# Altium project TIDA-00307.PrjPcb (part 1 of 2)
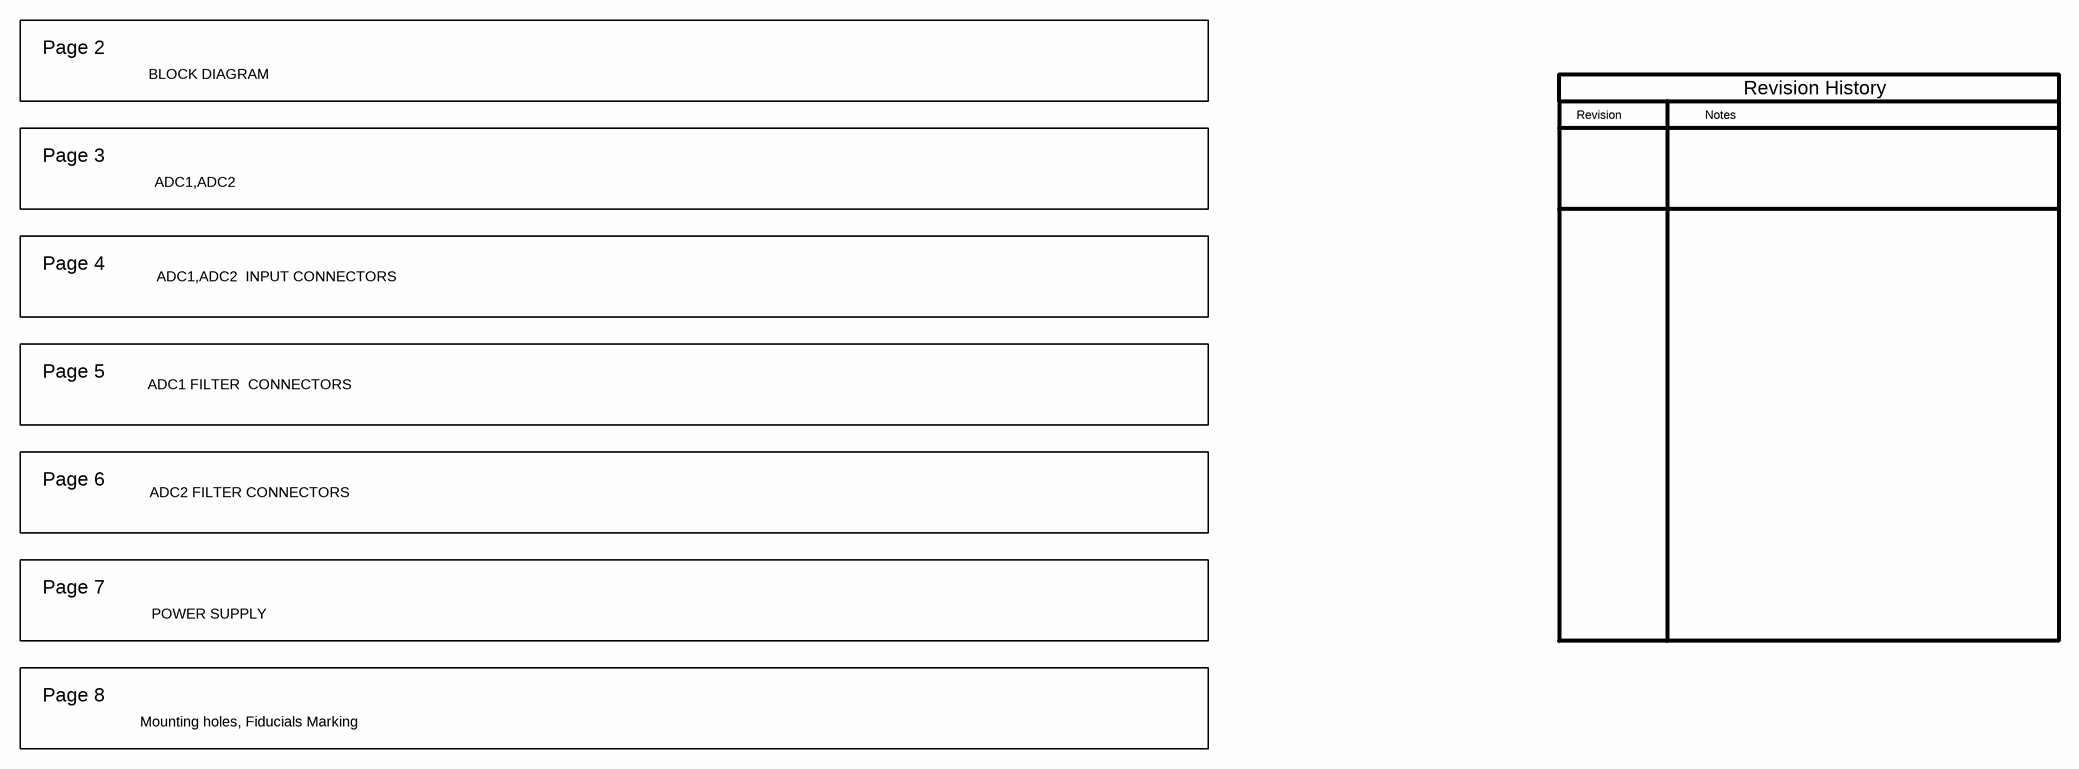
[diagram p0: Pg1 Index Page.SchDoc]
CopyrightYear: 2013; PCB_Layout: Who did the Layout?; PCB_Rev: E2; PRJ_Customer: Public Release; PRJ_Engineer: Srinivas K.; PRJ_Number: TIDA-00307; PRJ_Title: AFE-MERGING UNIT; SCH_Rev: E2; TechSupport: http://www.ti.com/support
8 sheets, 313 parts. Net scope: flat (ports and power ports of the same name join across sheets).
Board file: TIDA-00307_REV_E2.PcbDoc
Sheets:
  Pg1 Index Page.SchDoc
  Pg2 Block Diagram.SchDoc
  Pg3  ADC1,ADC2.SchDoc
  Pg4 ADC1,ADC2 INPUTS.SchDoc
  Pg5 ADC1 FILTERS.SchDoc
  Pg6 ADC2 FILTERS.SchDoc
  Pg7 Power Supply.SchDoc
  Pg8 Hardware.SchDoc

## Sheet Pg1 Index Page.SchDoc
size 431 x 279 mm; Date: Not shown in title block; ApprovedBy: Not shown in title block; CheckedBy: Not shown in title block; Author: Not shown in title block; CompanyName: Not shown in title block; Engineer: Not shown in title block; Organization: Not shown in title block; Address1: Not shown in title block; Address2: Not shown in title block; Address3: Not shown in title block; Address4: Not shown in title block; DocumentNumber: 1; Revision: E2; SheetNumber: 1; SheetTotal: 8; PageSetup: Record=PageOptions|CenterHorizontal=True|CenterVertical=True|PrintScale=1.00|XCorrection=1.00|YCorrection=1.00|PrintKind=0|BorderSize=5000000|LeftOffset=0|BottomOffset=0|Orientation=2|PaperLength=1000|PaperWidth=1000|Scale=100|PaperSource=15|PrintQuality=600|MediaType=1|DitherType=10|PaperKind=Letter|PrintScaleMode=1

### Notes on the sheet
- Page 2
- BLOCK DIAGRAM
- Revision
- Notes
- Revision History
- Page 3
- ADC1,ADC2
- Page 4
- ADC1,ADC2  INPUT CONNECTORS
- Page 5
- ADC1 FILTER  CONNECTORS
- Page 6
- ADC2 FILTER CONNECTORS
- Page 7
- POWER SUPPLY
- Page 8
- Mounting holes, Fiducials Marking

## Sheet Pg2 Block Diagram.SchDoc
size 431 x 279 mm; VersionControl_RevNumber: E2; Date: Not shown in title block; ApprovedBy: Not shown in title block; CheckedBy: Not shown in title block; Author: Not shown in title block; CompanyName: Not shown in title block; Engineer: Not shown in title block; Organization: Not shown in title block; Address1: Not shown in title block; Address2: Not shown in title block; Address3: Not shown in title block; Address4: Not shown in title block; DocumentNumber: 2; Revision: E2; SheetNumber: 2; SheetTotal: 8; PageSetup: Record=PageOptions|CenterHorizontal=True|CenterVertical=True|PrintScale=1.00|XCorrection=1.00|YCorrection=1.00|PrintKind=0|BorderSize=5000000|LeftOffset=0|BottomOffset=0|Orientation=2|PaperLength=1000|PaperWidth=1000|Scale=100|PaperSource=15|PrintQuality=600|MediaType=1|DitherType=10|PaperKind=Letter|PrintScaleMode=1
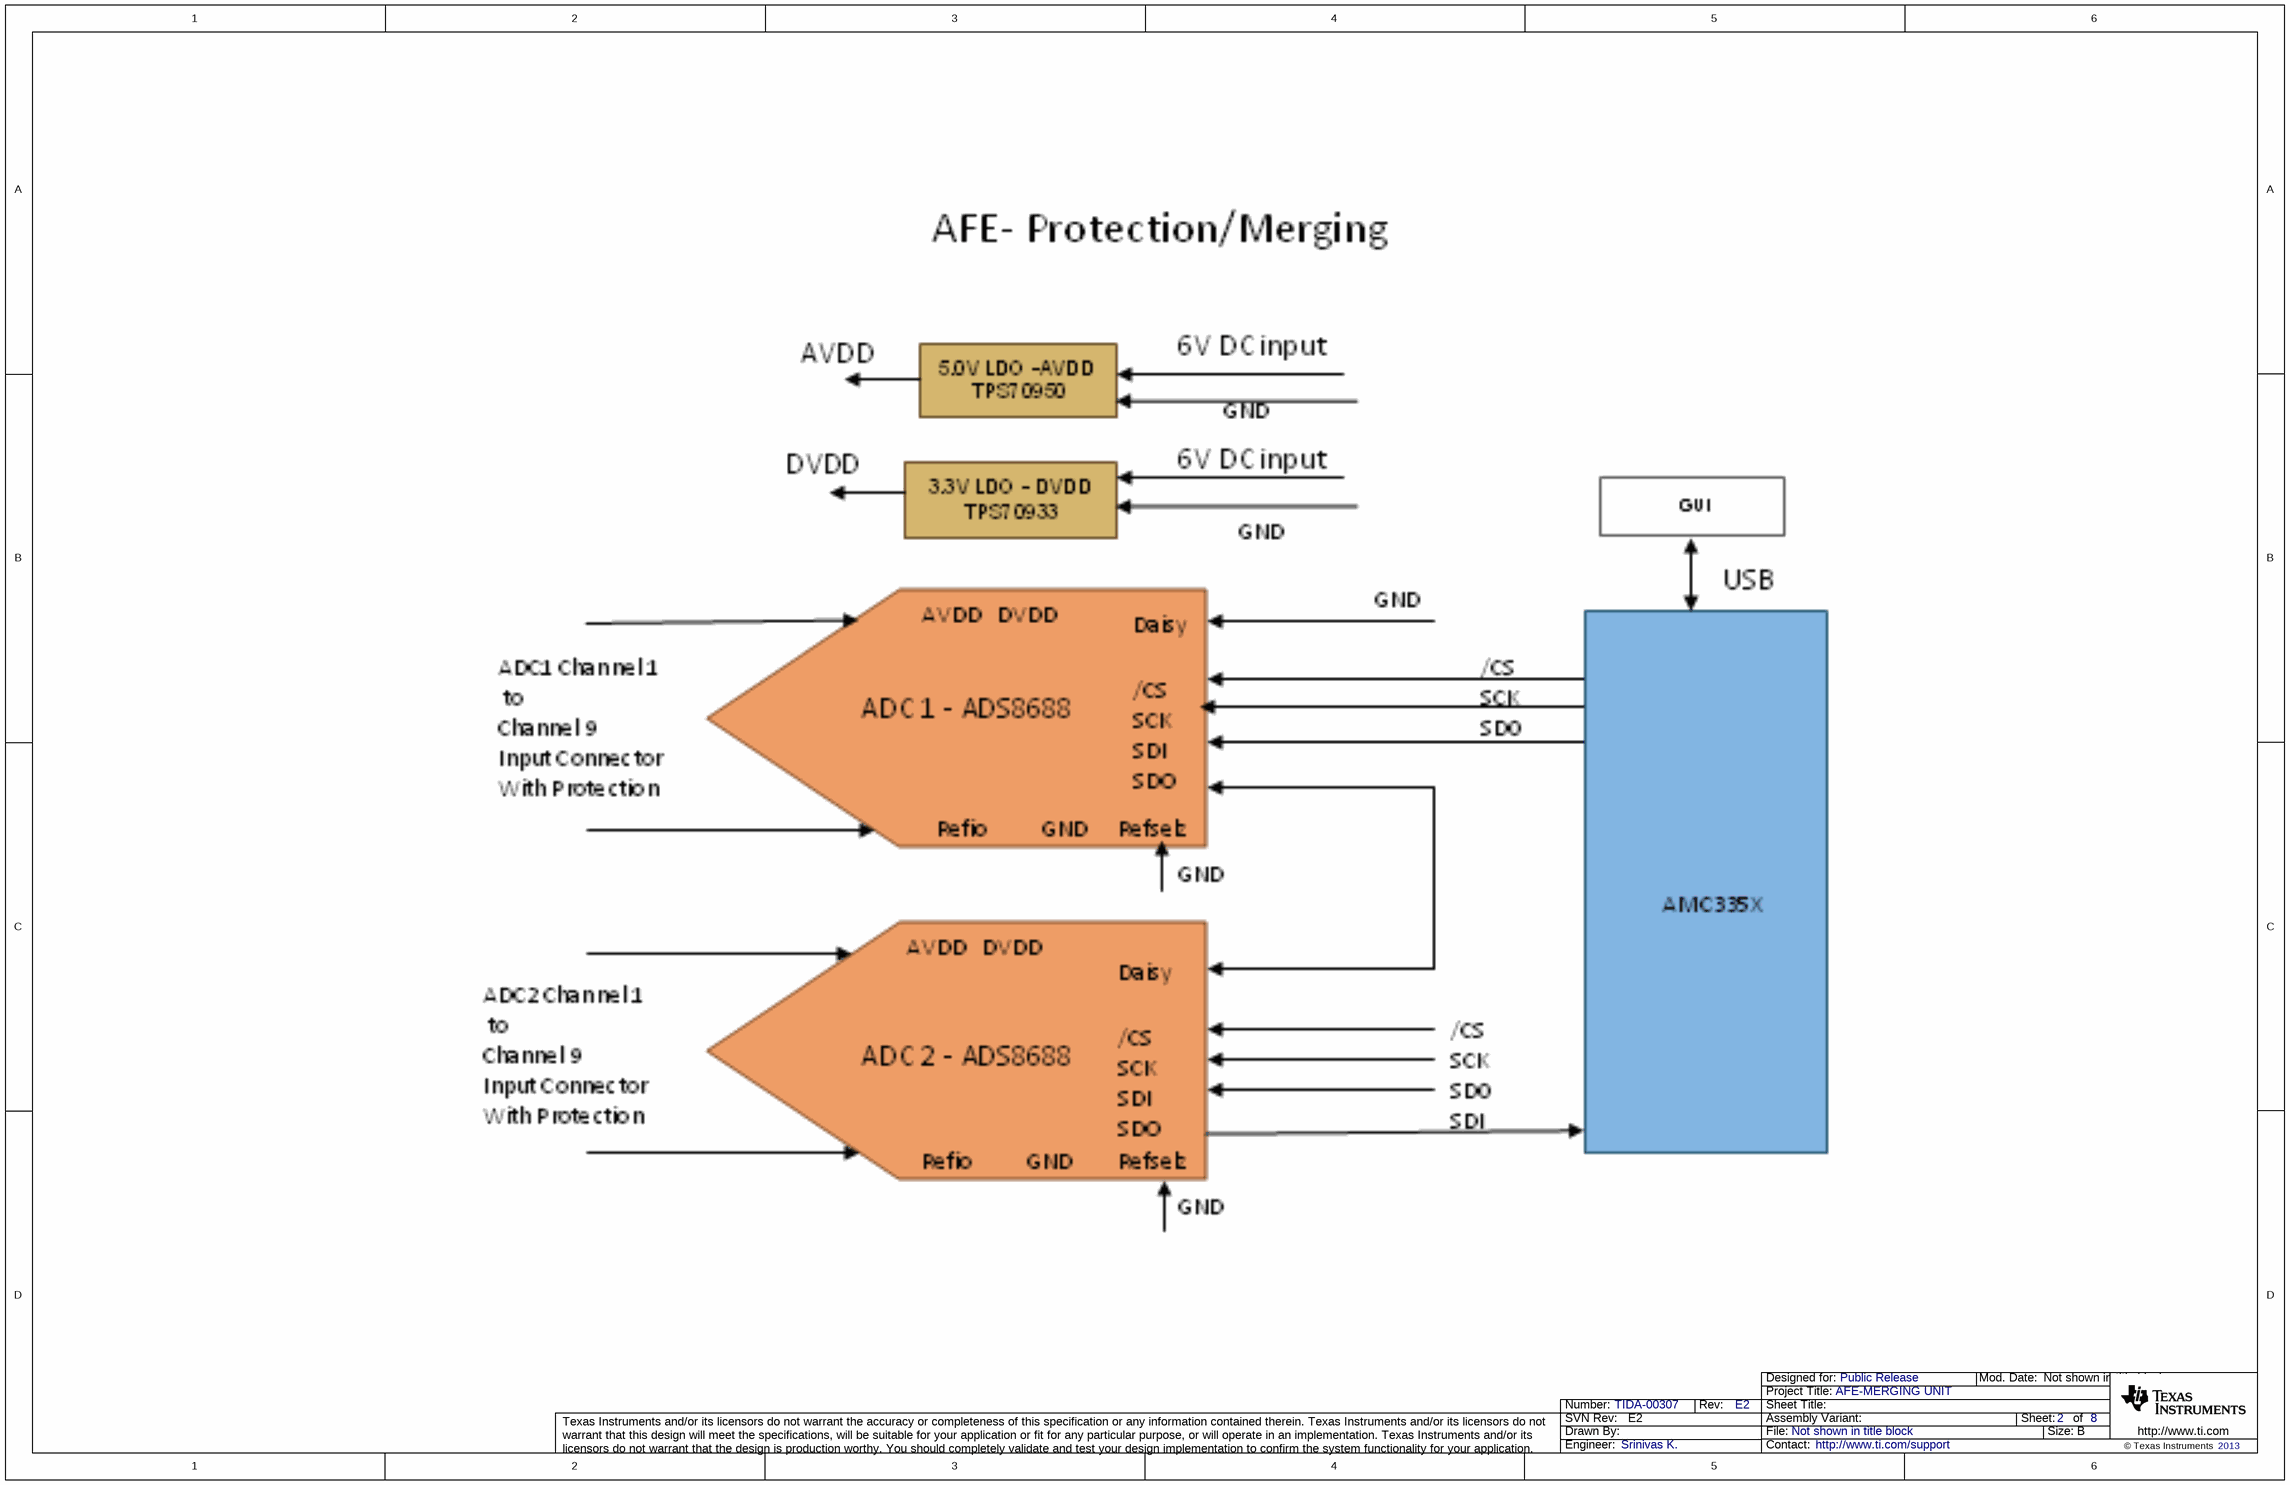
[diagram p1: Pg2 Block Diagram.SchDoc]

## Sheet Pg3  ADC1,ADC2.SchDoc
size 431 x 279 mm; Date: Not shown in title block; ApprovedBy: Not shown in title block; CheckedBy: Not shown in title block; Author: Not shown in title block; CompanyName: Not shown in title block; Engineer: Not shown in title block; Organization: Not shown in title block; Address1: Not shown in title block; Address2: Not shown in title block; Address3: Not shown in title block; Address4: Not shown in title block; DocumentNumber: 3; Revision: Use project parameter SCH_Rev; SheetNumber: 3; SheetTotal: 8; PageSetup: Record=PageOptions|CenterHorizontal=True|CenterVertical=True|PrintScale=1.00|XCorrection=1.00|YCorrection=1.00|PrintKind=0|BorderSize=5000000|LeftOffset=0|BottomOffset=0|Orientation=2|PaperLength=1000|PaperWidth=1000|Scale=100|PaperSource=15|PrintQuality=600|MediaType=1|DitherType=10|PaperKind=Letter|PrintScaleMode=1
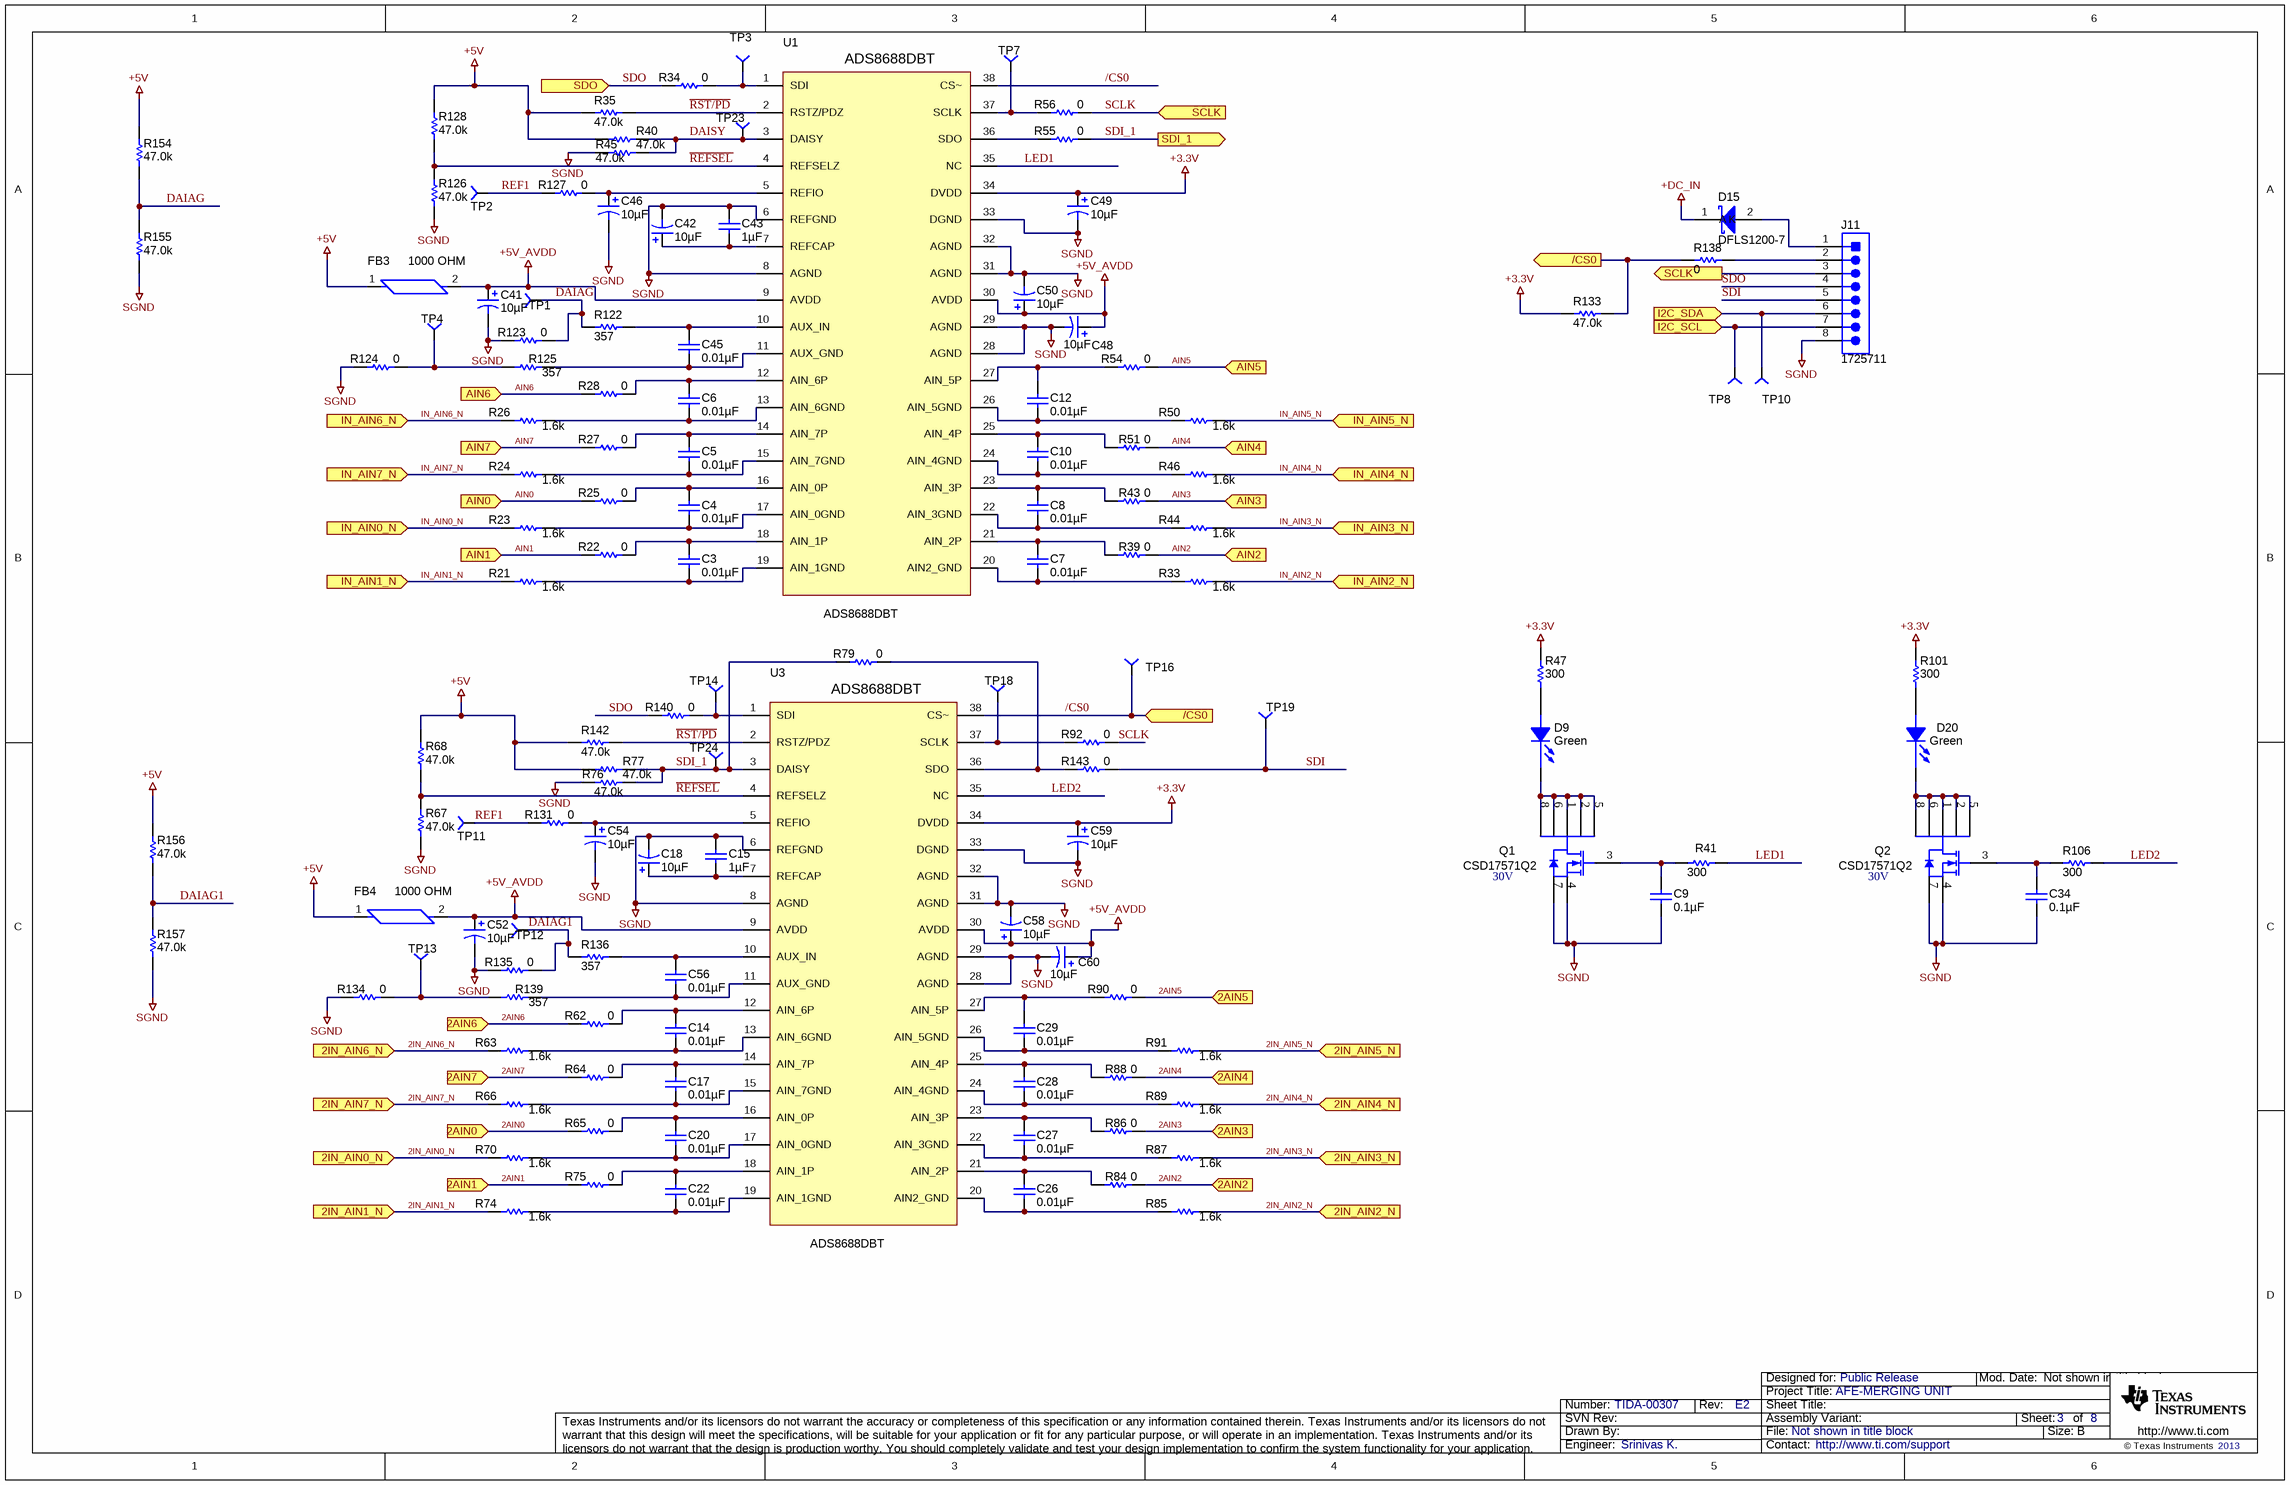
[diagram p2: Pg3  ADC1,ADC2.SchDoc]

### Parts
C3  ValueDisplayed: 0.01µF  [0603]  (hidden comment: 06031C103JAT2A)
C4  ValueDisplayed: 0.01µF  [0603]  (hidden comment: 06031C103JAT2A)
C5  ValueDisplayed: 0.01µF  [0603]  (hidden comment: 06031C103JAT2A)
C6  ValueDisplayed: 0.01µF  [0603]  (hidden comment: 06031C103JAT2A)
C7  ValueDisplayed: 0.01µF  [0603]  (hidden comment: 06031C103JAT2A)
C8  ValueDisplayed: 0.01µF  [0603]  (hidden comment: 06031C103JAT2A)
C9  ValueDisplayed: 0.1µF  [0603]  (hidden comment: 06033C104JAT2A)
C10  ValueDisplayed: 0.01µF  [0603]  (hidden comment: 06031C103JAT2A)
C12  ValueDisplayed: 0.01µF  [0603]  (hidden comment: 06031C103JAT2A)
C14  ValueDisplayed: 0.01µF  [0603]  (hidden comment: 06031C103JAT2A)
C15  ValueDisplayed: 1µF  [0603]  (hidden comment: EMK107B7105KA-T)
C17  ValueDisplayed: 0.01µF  [0603]  (hidden comment: 06031C103JAT2A)
C18  ValueDisplayed: 10µF  [3528-21]  (hidden comment: T491B106K016AT)
C20  ValueDisplayed: 0.01µF  [0603]  (hidden comment: 06031C103JAT2A)
C22  ValueDisplayed: 0.01µF  [0603]  (hidden comment: 06031C103JAT2A)
C26  ValueDisplayed: 0.01µF  [0603]  (hidden comment: 06031C103JAT2A)
C27  ValueDisplayed: 0.01µF  [0603]  (hidden comment: 06031C103JAT2A)
C28  ValueDisplayed: 0.01µF  [0603]  (hidden comment: 06031C103JAT2A)
C29  ValueDisplayed: 0.01µF  [0603]  (hidden comment: 06031C103JAT2A)
C34  ValueDisplayed: 0.1µF  [0603]  (hidden comment: 06033C104JAT2A)
C41  ValueDisplayed: 10µF  [3528-21]  (hidden comment: T491B106K016AT)
C42  ValueDisplayed: 10µF  [3528-21]  (hidden comment: T491B106K016AT)
C43  ValueDisplayed: 1µF  [0603]  (hidden comment: EMK107B7105KA-T)
C45  ValueDisplayed: 0.01µF  [0603]  (hidden comment: 06031C103JAT2A)
C46  ValueDisplayed: 10µF  [3528-21]  (hidden comment: T491B106K016AT)
C48  ValueDisplayed: 10µF  [3528-21]  (hidden comment: T491B106K016AT)
C49  ValueDisplayed: 10µF  [3528-21]  (hidden comment: T491B106K016AT)
C50  ValueDisplayed: 10µF  [3528-21]  (hidden comment: T491B106K016AT)
C52  ValueDisplayed: 10µF  [3528-21]  (hidden comment: T491B106K016AT)
C54  ValueDisplayed: 10µF  [3528-21]  (hidden comment: T491B106K016AT)
C56  ValueDisplayed: 0.01µF  [0603]  (hidden comment: 06031C103JAT2A)
C58  ValueDisplayed: 10µF  [3528-21]  (hidden comment: T491B106K016AT)
C59  ValueDisplayed: 10µF  [3528-21]  (hidden comment: T491B106K016AT)
C60  ValueDisplayed: 10µF  [3528-21]  (hidden comment: T491B106K016AT)
D9  value Green  [LED0603AA]  (hidden comment: LED_LG L29K-G2J1-24-Z)
D15  DFLS1200-7  [powerDI123]
D20  value Green  [LED0603AA]  (hidden comment: LED_LG L29K-G2J1-24-Z)
FB3  1000 OHM  [FB0603]
FB4  1000 OHM  [FB0603]
J11  1725711  [CONN_1725711]
Q1  CSD17571Q2  value 30V  [SON_CSD17571Q2]
Q2  CSD17571Q2  value 30V  [SON_CSD17571Q2]
R21  value 1.6k  [0603]  (hidden comment: CRCW06031K60JNEA)
R22  value 0  [0603]  (hidden comment: RC0603JR-070RL)
R23  value 1.6k  [0603]  (hidden comment: CRCW06031K60JNEA)
R24  value 1.6k  [0603]  (hidden comment: CRCW06031K60JNEA)
R25  value 0  [0603]  (hidden comment: RC0603JR-070RL)
R26  value 1.6k  [0603]  (hidden comment: CRCW06031K60JNEA)
R27  value 0  [0603]  (hidden comment: RC0603JR-070RL)
R28  value 0  [0603]  (hidden comment: RC0603JR-070RL)
R33  value 1.6k  [0603]  (hidden comment: CRCW06031K60JNEA)
R34  value 0  [0603]  (hidden comment: RC0603JR-070RL)
R35  value 47.0k  [0603]  (hidden comment: CRCW060347K0FKEA)
R39  value 0  [0603]  (hidden comment: RC0603JR-070RL)
R40  value 47.0k  [0603]  (hidden comment: CRCW060347K0FKEA)
R41  value 300  [0603]  (hidden comment: CRCW0603300RJNEA)
R43  value 0  [0603]  (hidden comment: RC0603JR-070RL)
R44  value 1.6k  [0603]  (hidden comment: CRCW06031K60JNEA)
R45  value 47.0k  [0603]  (hidden comment: CRCW060347K0FKEA)
R46  value 1.6k  [0603]  (hidden comment: CRCW06031K60JNEA)
R47  value 300  [0603]  (hidden comment: CRCW0603300RJNEA)
R50  value 1.6k  [0603]  (hidden comment: CRCW06031K60JNEA)
R51  value 0  [0603]  (hidden comment: RC0603JR-070RL)
R54  value 0  [0603]  (hidden comment: RC0603JR-070RL)
R55  value 0  [0603]  (hidden comment: RC0603JR-070RL)
R56  value 0  [0603]  (hidden comment: RC0603JR-070RL)
R62  value 0  [0603]  (hidden comment: RC0603JR-070RL)
R63  value 1.6k  [0603]  (hidden comment: CRCW06031K60JNEA)
R64  value 0  [0603]  (hidden comment: RC0603JR-070RL)
R65  value 0  [0603]  (hidden comment: RC0603JR-070RL)
R66  value 1.6k  [0603]  (hidden comment: CRCW06031K60JNEA)
R67  value 47.0k  [0603]  (hidden comment: CRCW060347K0FKEA)
R68  value 47.0k  [0603]  (hidden comment: CRCW060347K0FKEA)
R70  value 1.6k  [0603]  (hidden comment: CRCW06031K60JNEA)
R74  value 1.6k  [0603]  (hidden comment: CRCW06031K60JNEA)
R75  value 0  [0603]  (hidden comment: RC0603JR-070RL)
R76  value 47.0k  [0603]  (hidden comment: CRCW060347K0FKEA)
R77  value 47.0k  [0603]  (hidden comment: CRCW060347K0FKEA)
R79  value 0  [0603]  (hidden comment: RC0603JR-070RL)
R84  value 0  [0603]  (hidden comment: RC0603JR-070RL)
R85  value 1.6k  [0603]  (hidden comment: CRCW06031K60JNEA)
R86  value 0  [0603]  (hidden comment: RC0603JR-070RL)
R87  value 1.6k  [0603]  (hidden comment: CRCW06031K60JNEA)
R88  value 0  [0603]  (hidden comment: RC0603JR-070RL)
R89  value 1.6k  [0603]  (hidden comment: CRCW06031K60JNEA)
R90  value 0  [0603]  (hidden comment: RC0603JR-070RL)
R91  value 1.6k  [0603]  (hidden comment: CRCW06031K60JNEA)
R92  value 0  [0603]  (hidden comment: RC0603JR-070RL)
R101  value 300  [0603]  (hidden comment: CRCW0603300RJNEA)
R106  value 300  [0603]  (hidden comment: CRCW0603300RJNEA)
R122  value 357  [0603]  (hidden comment: CRCW0603357RFKEA)
R123  value 0  [0603]  (hidden comment: RC0603JR-070RL)
R124  value 0  [0603]  (hidden comment: RC0603JR-070RL)
R125  value 357  [0603]  (hidden comment: CRCW0603357RFKEA)
R126  value 47.0k  [0603]  (hidden comment: CRCW060347K0FKEA)
R127  value 0  [0603]  (hidden comment: RC0603JR-070RL)
R128  value 47.0k  [0603]  (hidden comment: CRCW060347K0FKEA)
R131  value 0  [0603]  (hidden comment: RC0603JR-070RL)
R133  value 47.0k  [0603]  (hidden comment: CRCW060347K0FKEA)
R134  value 0  [0603]  (hidden comment: RC0603JR-070RL)
R135  value 0  [0603]  (hidden comment: RC0603JR-070RL)
R136  value 357  [0603]  (hidden comment: CRCW0603357RFKEA)
R138  value 0  [0603]  (hidden comment: RC0603JR-070RL)
R139  value 357  [0603]  (hidden comment: CRCW0603357RFKEA)
R140  value 0  [0603]  (hidden comment: RC0603JR-070RL)
R142  value 47.0k  [0603]  (hidden comment: CRCW060347K0FKEA)
R143  value 0  [0603]  (hidden comment: RC0603JR-070RL)
R154  value 47.0k  [0603]  (hidden comment: CRCW060347K0FKEA)
R155  value 47.0k  [0603]  (hidden comment: CRCW060347K0FKEA)
R156  value 47.0k  [0603]  (hidden comment: CRCW060347K0FKEA)
R157  value 47.0k  [0603]  (hidden comment: CRCW060347K0FKEA)
TP1  TP1_PD40_D0.5_S50  [TP1_PD40_D0.5_S50]  (value not drawn)
TP2  TP1_PD40_D0.5_S50  [TP1_PD40_D0.5_S50]  (value not drawn)
TP3  TP1_PD40_D0.5_S50  [TP1_PD40_D0.5_S50]  (value not drawn)
TP4  TP1_PD40_D0.5_S50  [TP1_PD40_D0.5_S50]  (value not drawn)
TP7  TP1_PD40_D0.5_S50  [TP1_PD40_D0.5_S50]  (value not drawn)
TP8  TP1_PD40_D0.5_S50  [TP1_PD40_D0.5_S50]  (value not drawn)
TP10  TP1_PD40_D0.5_S50  [TP1_PD40_D0.5_S50]  (value not drawn)
TP11  TP1_PD40_D0.5_S50  [TP1_PD40_D0.5_S50]  (value not drawn)
TP12  TP1_PD40_D0.5_S50  [TP1_PD40_D0.5_S50]  (value not drawn)
TP13  TP1_PD40_D0.5_S50  [TP1_PD40_D0.5_S50]  (value not drawn)
TP14  TP1_PD40_D0.5_S50  [TP1_PD40_D0.5_S50]  (value not drawn)
TP16  TP1_PD40_D0.5_S50  [TP1_PD40_D0.5_S50]  (value not drawn)
TP18  TP1_PD40_D0.5_S50  [TP1_PD40_D0.5_S50]  (value not drawn)
TP19  TP1_PD40_D0.5_S50  [TP1_PD40_D0.5_S50]  (value not drawn)
TP23  TP1_PD40_D0.5_S50  [TP1_PD40_D0.5_S50]  (value not drawn)
TP24  TP1_PD40_D0.5_S50  [TP1_PD40_D0.5_S50]  (value not drawn)
U1  ADS8688DBT  [DBT0038A_M]
U3  ADS8688DBT  [DBT0038A_M]

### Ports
2AIN0 (in), 2AIN1 (in), 2AIN2 (in), 2AIN3 (in), 2AIN4 (in), 2AIN5 (in), 2AIN6 (in), 2AIN7 (in), 2IN_AIN0_N (in), 2IN_AIN1_N (in), 2IN_AIN2_N (in), 2IN_AIN3_N (in), 2IN_AIN4_N (in), 2IN_AIN5_N (in), 2IN_AIN6_N (in), 2IN_AIN7_N (in), /CS0 (in), /CS0 (out), AIN0 (in), AIN1 (in), AIN2 (in), AIN3 (in), AIN4 (in), AIN5 (in), AIN6 (in), AIN7 (in), I2C_SCL (in), I2C_SDA (in), IN_AIN0_N (in), IN_AIN1_N (in), IN_AIN2_N (in), IN_AIN3_N (in), IN_AIN4_N (in), IN_AIN5_N (in), IN_AIN6_N (in), IN_AIN7_N (in), SCLK (in), SCLK (out), SDI_1 (out), SDO (in)

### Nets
+3.3V: C49.1(+) C59.1(+) R47.2 R101.2 R133.1 U1.34(DVDD) U3.34(DVDD)
+5V: FB3.1 FB4.1 R35.1 R40.1 R68.1 R77.1 R128.1 R142.1 R154.2 R156.2
+5V_AVDD: C41.1(+) C48.1(+) C50.1(+) C52.1(+) C58.1(+) C60.1(+) FB3.2 FB4.2 U1.9(AVDD) U1.30(AVDD) U3.9(AVDD) U3.30(AVDD)
+DC_IN: D15.1(K)
SGND: C9.2 C15.1 C18.2(-) C34.2 C41.2(-) C42.2(-) C43.1 C46.2(-) C48.2(-) C49.2(-) C50.2(-) C52.2(-) C54.2(-) C58.2(-) C59.2(-) C60.2(-) J11.8 Q1.4(S) Q1.7(S) Q2.4(S) Q2.7(S) R45.1 R67.2 R76.1 R123.1 R124.1 R126.2 R134.1 R135.1 R155.1 R157.1 U1.6(REFGND) U1.8(AGND) U1.28(AGND) U1.29(AGND) U1.31(AGND) U1.32(AGND) U1.33(DGND) U3.6(REFGND) U3.8(AGND) U3.28(AGND) U3.29(AGND) U3.31(AGND) U3.32(AGND) U3.33(DGND)
2AIN0: R65.1 ; port 2AIN0
2AIN1: R75.1 ; port 2AIN1
2AIN2: R84.2 ; port 2AIN2
2AIN3: R86.2 ; port 2AIN3
2AIN4: R88.2 ; port 2AIN4
2AIN5: R90.2 ; port 2AIN5
2AIN6: R62.1 ; port 2AIN6
2AIN7: R64.1 ; port 2AIN7
2IN_AIN0_N: R70.1 ; port 2IN_AIN0_N
2IN_AIN1_N: R74.1 ; port 2IN_AIN1_N
2IN_AIN2_N: R85.2 ; port 2IN_AIN2_N
2IN_AIN3_N: R87.2 ; port 2IN_AIN3_N
2IN_AIN4_N: R89.2 ; port 2IN_AIN4_N
2IN_AIN5_N: R91.2 ; port 2IN_AIN5_N
2IN_AIN6_N: R63.1 ; port 2IN_AIN6_N
2IN_AIN7_N: R66.1 ; port 2IN_AIN7_N
/CS0: R133.2 R138.2 TP16.1 U1.38(CS~) U3.38(CS~) ; port /CS0
~{REFSEL}: R67.1 R68.2 R126.1 R128.2 U1.4(REFSELZ) U3.4(REFSELZ)
~{RST/PD}: R35.2 R142.2 U1.2(RSTZ/PDZ) U3.2(RSTZ/PDZ)
AIN0: R25.1 ; port AIN0
AIN1: R22.1 ; port AIN1
AIN2: R39.2 ; port AIN2
AIN3: R43.2 ; port AIN3
AIN4: R51.2 ; port AIN4
AIN5: R54.2 ; port AIN5
AIN6: R28.1 ; port AIN6
AIN7: R27.1 ; port AIN7
DAIAG: R122.1 R123.2 R154.1 R155.2 TP1.1
DAIAG1: R135.2 R136.1 R156.1 R157.2 TP12.1
DAISY: R40.2 R45.2 TP23.1 U1.3(DAISY)
I2C_SCL: J11.7 TP8.1 ; port I2C_SCL
I2C_SDA: J11.6 TP10.1 ; port I2C_SDA
IN_AIN0_N: R23.1 ; port IN_AIN0_N
IN_AIN1_N: R21.1 ; port IN_AIN1_N
IN_AIN2_N: R33.2 ; port IN_AIN2_N
IN_AIN3_N: R44.2 ; port IN_AIN3_N
IN_AIN4_N: R46.2 ; port IN_AIN4_N
IN_AIN5_N: R50.2 ; port IN_AIN5_N
IN_AIN6_N: R26.1 ; port IN_AIN6_N
IN_AIN7_N: R24.1 ; port IN_AIN7_N
LED1: R41.1 U1.35(NC)
LED2: R106.1 U3.35(NC)
REF1: R127.1 R131.1 TP2.1 TP11.1
SCLK: J11.3 R56.2 R92.2 ; port SCLK
SDI: J11.5 R143.2 TP19.1
SDI_1: R55.2 R76.2 R77.2 R79.1 TP24.1 U3.3(DAISY) ; port SDI_1
SDO: J11.4 R34.1 R140.1 ; port SDO
NetC3_1: C3.1 R22.2 U1.18(AIN_1P)
NetC3_2: C3.2 R21.2 U1.19(AIN_1GND)
NetC4_1: C4.1 R25.2 U1.16(AIN_0P)
NetC4_2: C4.2 R23.2 U1.17(AIN_0GND)
NetC5_1: C5.1 R27.2 U1.14(AIN_7P)
NetC5_2: C5.2 R24.2 U1.15(AIN_7GND)
NetC6_1: C6.1 R28.2 U1.12(AIN_6P)
NetC6_2: C6.2 R26.2 U1.13(AIN_6GND)
NetC7_1: C7.1 R39.1 U1.21(AIN_2P)
NetC7_2: C7.2 R33.1 U1.20(AIN2_GND)
NetC8_1: C8.1 R43.1 U1.23(AIN_3P)
NetC8_2: C8.2 R44.1 U1.22(AIN_3GND)
NetC9_1: C9.1 Q1.3(G) R41.2
NetC10_1: C10.1 R51.1 U1.25(AIN_4P)
NetC10_2: C10.2 R46.1 U1.24(AIN_4GND)
NetC12_1: C12.1 R54.1 U1.27(AIN_5P)
NetC12_2: C12.2 R50.1 U1.26(AIN_5GND)
NetC14_1: C14.1 R62.2 U3.12(AIN_6P)
NetC14_2: C14.2 R63.2 U3.13(AIN_6GND)
NetC15_2: C15.2 C18.1(+) U3.7(REFCAP)
NetC17_1: C17.1 R64.2 U3.14(AIN_7P)
NetC17_2: C17.2 R66.2 U3.15(AIN_7GND)
NetC20_1: C20.1 R65.2 U3.16(AIN_0P)
NetC20_2: C20.2 R70.2 U3.17(AIN_0GND)
NetC22_1: C22.1 R75.2 U3.18(AIN_1P)
NetC22_2: C22.2 R74.2 U3.19(AIN_1GND)
NetC26_1: C26.1 R84.1 U3.21(AIN_2P)
NetC26_2: C26.2 R85.1 U3.20(AIN2_GND)
NetC27_1: C27.1 R86.1 U3.23(AIN_3P)
NetC27_2: C27.2 R87.1 U3.22(AIN_3GND)
NetC28_1: C28.1 R88.1 U3.25(AIN_4P)
NetC28_2: C28.2 R89.1 U3.24(AIN_4GND)
NetC29_1: C29.1 R90.1 U3.27(AIN_5P)
NetC29_2: C29.2 R91.1 U3.26(AIN_5GND)
NetC34_1: C34.1 Q2.3(G) R106.2
NetC42_1: C42.1(+) C43.2 U1.7(REFCAP)
NetC45_1: C45.1 R122.2 U1.10(AUX_IN)
NetC45_2: C45.2 R125.2 U1.11(AUX_GND)
NetC46_1: C46.1(+) R127.2 U1.5(REFIO)
NetC54_1: C54.1(+) R131.2 U3.5(REFIO)
NetC56_1: C56.1 R136.2 U3.10(AUX_IN)
NetC56_2: C56.2 R139.2 U3.11(AUX_GND)
NetD9_1: D9.1(C) Q1.1(D) Q1.2(D) Q1.5(D) Q1.6(D) Q1.8(D)
NetD9_2: D9.2(A) R47.1
NetD15_2: D15.2(A) J11.1
NetD20_1: D20.1(C) Q2.1(D) Q2.2(D) Q2.5(D) Q2.6(D) Q2.8(D)
NetD20_2: D20.2(A) R101.1
NetJ11_2: J11.2 R138.1
NetR34_2: R34.2 TP3.1 U1.1(SDI)
NetR55_1: R55.1 U1.36(SDO)
NetR56_1: R56.1 TP7.1 U1.37(SCLK)
NetR79_2: R79.2 R143.1 U3.36(SDO)
NetR92_1: R92.1 TP18.1 U3.37(SCLK)
NetR124_2: R124.2 R125.1 TP4.1
NetR134_2: R134.2 R139.1 TP13.1
NetR140_2: R140.2 TP14.1 U3.1(SDI)

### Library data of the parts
C3-C8 C10 C12 C14 C17 C20 C22 C26-C29 C45 C56 = 06031C103JAT2A: CAP, CERM, 0.01uF, 100V, +/-5%, X7R, 0603; Manufacturer: AVX; Polarized: N; CompType: Capacitor; U/M: EA; Cap_F: 0.00000001; Tolerance_%: 5; ESR_Ohm: 0.098; Value1: 0.098 ohm; VDC_V: 100; TaMin_C: -55; TaMax_C: 125
C9 C34 = 06033C104JAT2A: CAP, CERM, 0.1uF, 25V, +/-5%, X7R, 0603; Manufacturer: AVX; Polarized: N; CompType: Capacitor; U/M: EA; Cap_F: 0.0000001; Tolerance_%: 5; ESR_Ohm: 0.05; Value1: 0.05 ohm; VDC_V: 25; TaMin_C: -55; TaMax_C: 125
C15 C43 = EMK107B7105KA-T: CAP, CERM, 1uF, 16V, +/-10%, X7R, 0603; Manufacturer: Taiyo Yuden; Polarized: N; CompType: Capacitor; U/M: EA; Cap_F: 0.000001; Tolerance_%: 10; Value1: Unknown; VDC_V: 16; TaMin_C: -55; TaMax_C: 85
C18 C41 C42 C46 C48-C50 C52 C54 C58-C60 = 293D106X9016B2TE3: CAP, TA, 10 µF, 16 V, +/- 10%, 2 ohm, SMD; Manufacturer: Vishay-Sprague; Polarized: Y; CompType: Capacitor; Value: 10uF; U/M: EA; Cap_F: 0.00001; Tolerance_%: 10; Value1: 2 ohm; VDC_V: 16; Value2: 16V; ESR_ohm: 2; IRMS_A: 0.21; TaMin_C: -55; TaMax_C: 125; Cap_Case: B
D9 D20 = LED_LG L29K-G2J1-24-Z: LED SmartLED Green 570NM; Manufacturer: OSRAM; SymbolCreator: x0120606
D15 = DFLS1200-7: Diode, Schottky, 200V, 1A, PowerDI123; Manufacturer: Diodes Inc.; U/M: EA; Vf_V: 0.85; Value2: 0.85V; Io_A: 1; Vr_V: 200; TJmax_C: 175; RJC_CperW: 7
FB3 FB4 = MMZ1608B102C: FERRITE CHIP 1000 OHM 300MA 0603; Manufacturer: TDK Corporation; CompType: Ferrite Bead
J11 = 1725711: Terminal Block, 8x1, 2.54 mm, TH; Manufacturer: Phoenix Contact; SymbolCreator: a0411947; U/M: EA
Q1 Q2 = CSD17571Q2: MOSFET, N-CH, 30V, 22A, SON 2X2 MM; Manufacturer: TEXAS INSTRUMENTS; CompType: POWER MOSFET
R21 R23 R24 R26 R33 R44 R46 R50 R63 R66 R70 R74 R85 R87 R89 R91 = CRCW06031K60JNEA: RES, 1.6k ohm, 5%, 0.1W, 0603; Manufacturer: Vishay-Dale; CompType: Resistor; Res_ohm: 1600; Value_Code: 1k60; Tolerance_%: 5; Power_W: 0.1; VDC_V: 75; TempCo: 200 ppm/C; EIA_Code: E24; U/M: EA
R22 R25 R27 R28 R34 R39 R43 R51 R54-R56 R62 R64 R65 R75 R79 R84 R86 R88 R90 R92 R123 R124 R127 R131 R134 R135 R138 R140 R143 = RC0402JR-070RL: RES, 0 ohm,5%, 0.1W, 0603; Manufacturer: Yageo America; CompType: Resistor; Value_Code: 0000; Tolerance_%: 5; Power_W: 0.1; VDC_V: 50; TempCo: 200 ppm/C; EIA_Code: E24; U/M: EA
R35 R40 R45 R67 R68 R76 R77 R126 R128 R133 R142 R154-R157 = RT0603BRD0747KL: RES, 47.0k ohm, 1%, 0.1W, 0603; Manufacturer: Vishay Dale; CompType: Resistor; Res_ohm: 47000; Value_Code: 47k0; Tolerance_%: 1; Power_W: 0.1; VDC_V: 75; TempCo: 25 ppm/C; EIA_Code: E192; U/M: EA
R41 R47 R101 R106 = CRCW0603300RJNEA: RES, 300 ohm, 5%, 0.1W, 0603; Manufacturer: Vishay-Dale; CompType: Resistor; Value_Code: 300R; Tolerance_%: 5; Power_W: 0.1; VDC_V: 75; TempCo: 200 ppm/C; EIA_Code: E24; U/M: EA
R122 R125 R136 R139 = CRCW0603357RFKEA: RES, 357 ohm, 1%, 0.1W, 0603; Manufacturer: Vishay-Dale; CompType: Resistor; Value_Code: 357R; Tolerance_%: 1; Power_W: 0.1; VDC_V: 75; TempCo: 100 ppm/C; EIA_Code: E96; U/M: EA
TP1-TP4 TP7 TP8 TP10-TP14 TP16 TP18 TP19 TP23 TP24 = TP-040_RND: Test Point 40mil pad 20mil drill; Manufacturer: STD; Description: Test Point, O.040 Hole; Value: STD
U1 U3 = ADS8688DBT: 16 bit 400KSPS 8 Channel SAR ADC; Manufacturer: TI; Alternate Manufacturer: None; SymbolCreator: a0393903; CompType: ADC IC; U/M: EA, IN, or GM

## Sheet Pg4 ADC1,ADC2 INPUTS.SchDoc
size 431 x 279 mm; Date: Not shown in title block; ApprovedBy: Not shown in title block; CheckedBy: Not shown in title block; Author: Not shown in title block; CompanyName: Not shown in title block; Engineer: Not shown in title block; Organization: Not shown in title block; Address1: Not shown in title block; Address2: Not shown in title block; Address3: Not shown in title block; Address4: Not shown in title block; DocumentNumber: 8; Revision: Use project parameter SCH_Rev; SheetNumber: 4; SheetTotal: 8; PageSetup: Record=PageOptions|CenterHorizontal=True|CenterVertical=True|PrintScale=1.00|XCorrection=1.00|YCorrection=1.00|PrintKind=0|BorderSize=5000000|LeftOffset=0|BottomOffset=0|Orientation=2|PaperLength=1000|PaperWidth=1000|Scale=100|PaperSource=15|PrintQuality=600|MediaType=1|DitherType=10|PaperKind=Letter|PrintScaleMode=1
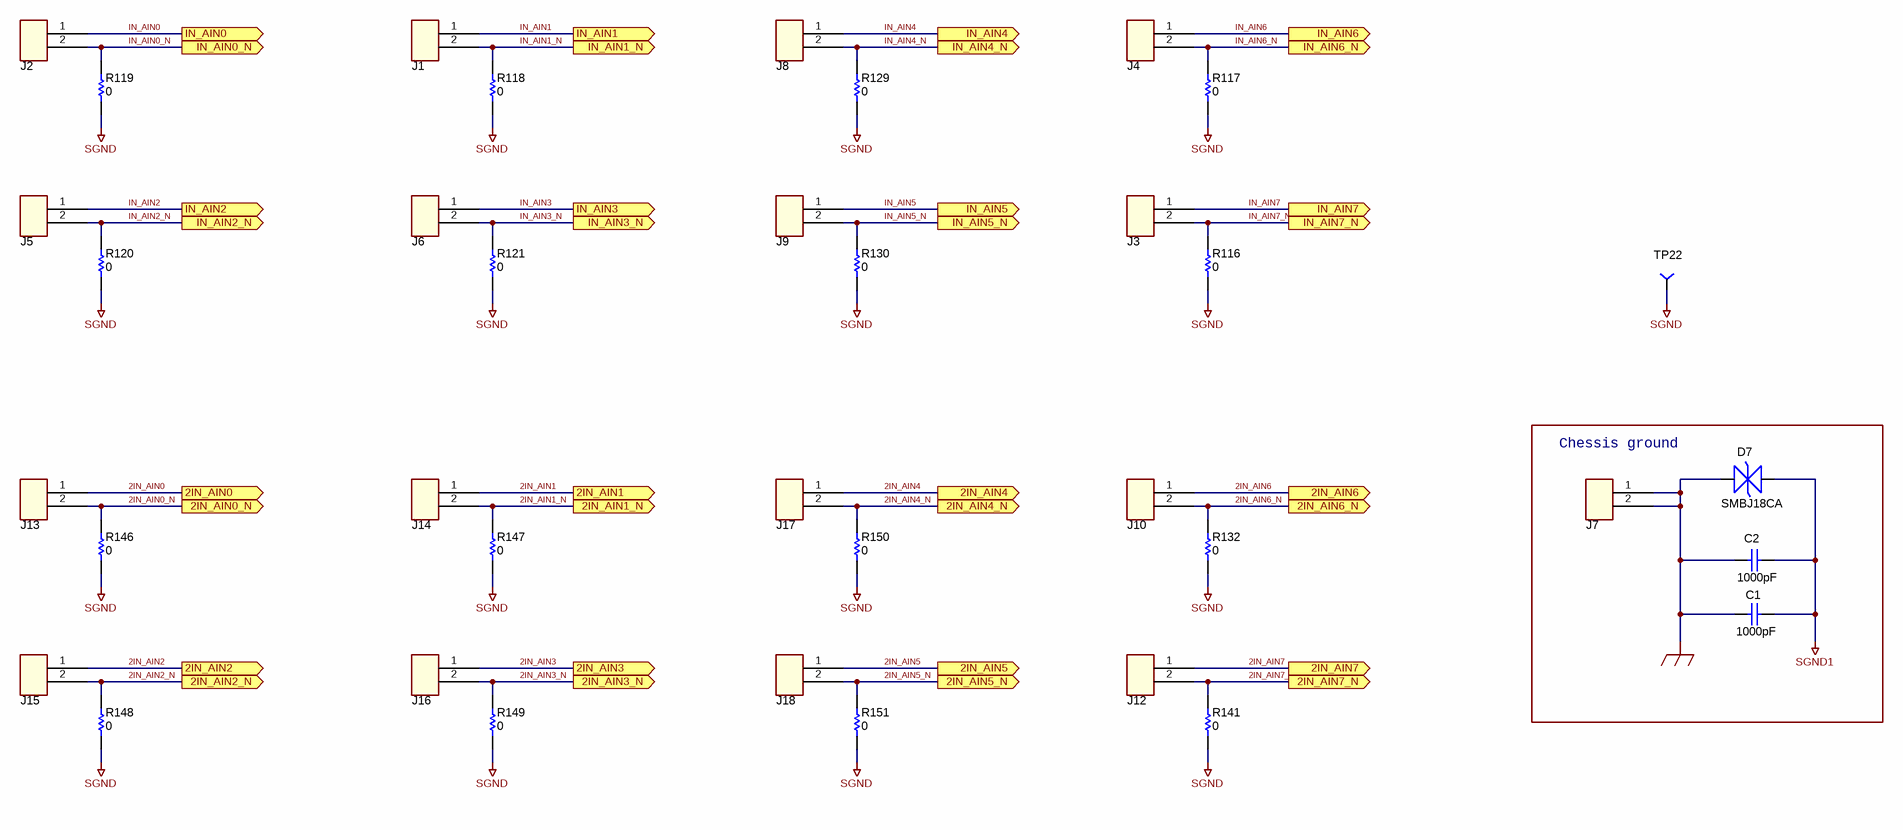
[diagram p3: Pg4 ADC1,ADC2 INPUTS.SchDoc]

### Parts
C1  value 1000pF  [1206]  (hidden comment: 202R18W102KV4E)
C2  value 1000pF  [1206]  (hidden comment: 202R18W102KV4E)
D7  SMBJ18CA  [DIO_SMB_BIAAAA]
J1  CON-OSTVN02A150  [CN2_MTB_P100_PD80_D1.1_S5.54X6.5_STACK]  (value not drawn)
J2  CON-OSTVN02A150  [CN2_MTB_P100_PD80_D1.1_S5.54X6.5_STACK]  (value not drawn)
J3  CON-OSTVN02A150  [CN2_MTB_P100_PD80_D1.1_S5.54X6.5_STACK]  (value not drawn)
J4  CON-OSTVN02A150  [CN2_MTB_P100_PD80_D1.1_S5.54X6.5_STACK]  (value not drawn)
J5  CON-OSTVN02A150  [CN2_MTB_P100_PD80_D1.1_S5.54X6.5_STACK]  (value not drawn)
J6  CON-OSTVN02A150  [CN2_MTB_P100_PD80_D1.1_S5.54X6.5_STACK]  (value not drawn)
J7  CON-OSTVN02A150  [CN2_MTB_P100_PD80_D1.1_S5.54X6.5_STACK]  (value not drawn)
J8  CON-OSTVN02A150  [CN2_MTB_P100_PD80_D1.1_S5.54X6.5_STACK]  (value not drawn)
J9  CON-OSTVN02A150  [CN2_MTB_P100_PD80_D1.1_S5.54X6.5_STACK]  (value not drawn)
J10  CON-OSTVN02A150  [CN2_MTB_P100_PD80_D1.1_S5.54X6.5_STACK]  (value not drawn)
J12  CON-OSTVN02A150  [CN2_MTB_P100_PD80_D1.1_S5.54X6.5_STACK]  (value not drawn)
J13  CON-OSTVN02A150  [CN2_MTB_P100_PD80_D1.1_S5.54X6.5_STACK]  (value not drawn)
J14  CON-OSTVN02A150  [CN2_MTB_P100_PD80_D1.1_S5.54X6.5_STACK]  (value not drawn)
J15  CON-OSTVN02A150  [CN2_MTB_P100_PD80_D1.1_S5.54X6.5_STACK]  (value not drawn)
J16  CON-OSTVN02A150  [CN2_MTB_P100_PD80_D1.1_S5.54X6.5_STACK]  (value not drawn)
J17  CON-OSTVN02A150  [CN2_MTB_P100_PD80_D1.1_S5.54X6.5_STACK]  (value not drawn)
J18  CON-OSTVN02A150  [CN2_MTB_P100_PD80_D1.1_S5.54X6.5_STACK]  (value not drawn)
R116  value 0  [1206]  (hidden comment: RC1206JR-070RL)
R117  value 0  [1206]  (hidden comment: RC1206JR-070RL)
R118  value 0  [1206]  (hidden comment: RC1206JR-070RL)
R119  value 0  [1206]  (hidden comment: RC1206JR-070RL)
R120  value 0  [1206]  (hidden comment: RC1206JR-070RL)
R121  value 0  [1206]  (hidden comment: RC1206JR-070RL)
R129  value 0  [1206]  (hidden comment: RC1206JR-070RL)
R130  value 0  [1206]  (hidden comment: RC1206JR-070RL)
R132  value 0  [1206]  (hidden comment: RC1206JR-070RL)
R141  value 0  [1206]  (hidden comment: RC1206JR-070RL)
R146  value 0  [1206]  (hidden comment: RC1206JR-070RL)
R147  value 0  [1206]  (hidden comment: RC1206JR-070RL)
R148  value 0  [1206]  (hidden comment: RC1206JR-070RL)
R149  value 0  [1206]  (hidden comment: RC1206JR-070RL)
R150  value 0  [1206]  (hidden comment: RC1206JR-070RL)
R151  value 0  [1206]  (hidden comment: RC1206JR-070RL)
TP22  TP1_PD40_D0.5_S50  [TP1_PD40_D0.5_S50]  (value not drawn)

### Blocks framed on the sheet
Chessis ground: C1 C2 D7 J7

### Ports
2IN_AIN0 (out), 2IN_AIN0_N (out), 2IN_AIN1 (out), 2IN_AIN1_N (out), 2IN_AIN2 (out), 2IN_AIN2_N (out), 2IN_AIN3 (out), 2IN_AIN3_N (out), 2IN_AIN4 (out), 2IN_AIN4_N (out), 2IN_AIN5 (out), 2IN_AIN5_N (out), 2IN_AIN6 (out), 2IN_AIN6_N (out), 2IN_AIN7 (out), 2IN_AIN7_N (out), IN_AIN0 (out), IN_AIN0_N (out), IN_AIN1 (out), IN_AIN1_N (out), IN_AIN2 (out), IN_AIN2_N (out), IN_AIN3 (out), IN_AIN3_N (out), IN_AIN4 (out), IN_AIN4_N (out), IN_AIN5 (out), IN_AIN5_N (out), IN_AIN6 (out), IN_AIN6_N (out), IN_AIN7 (out), IN_AIN7_N (out)

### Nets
GND_EARTH: C1.2 C2.2 D7.2 J7.1 J7.2
SGND: R116.1 R117.1 R118.1 R119.1 R120.1 R121.1 R129.1 R130.1 R132.1 R141.1 R146.1 R147.1 R148.1 R149.1 R150.1 R151.1 TP22.1
SGND1: C1.1 C2.1 D7.1
2IN_AIN0: J13.1 ; port 2IN_AIN0
2IN_AIN0_N: J13.2 R146.2 ; port 2IN_AIN0_N
2IN_AIN1: J14.1 ; port 2IN_AIN1
2IN_AIN1_N: J14.2 R147.2 ; port 2IN_AIN1_N
2IN_AIN2: J15.1 ; port 2IN_AIN2
2IN_AIN2_N: J15.2 R148.2 ; port 2IN_AIN2_N
2IN_AIN3: J16.1 ; port 2IN_AIN3
2IN_AIN3_N: J16.2 R149.2 ; port 2IN_AIN3_N
2IN_AIN4: J17.1 ; port 2IN_AIN4
2IN_AIN4_N: J17.2 R150.2 ; port 2IN_AIN4_N
2IN_AIN5: J18.1 ; port 2IN_AIN5
2IN_AIN5_N: J18.2 R151.2 ; port 2IN_AIN5_N
2IN_AIN6: J10.1 ; port 2IN_AIN6
2IN_AIN6_N: J10.2 R132.2 ; port 2IN_AIN6_N
2IN_AIN7: J12.1 ; port 2IN_AIN7
2IN_AIN7_N: J12.2 R141.2 ; port 2IN_AIN7_N
IN_AIN0: J2.1 ; port IN_AIN0
IN_AIN0_N: J2.2 R119.2 ; port IN_AIN0_N
IN_AIN1: J1.1 ; port IN_AIN1
IN_AIN1_N: J1.2 R118.2 ; port IN_AIN1_N
IN_AIN2: J5.1 ; port IN_AIN2
IN_AIN2_N: J5.2 R120.2 ; port IN_AIN2_N
IN_AIN3: J6.1 ; port IN_AIN3
IN_AIN3_N: J6.2 R121.2 ; port IN_AIN3_N
IN_AIN4: J8.1 ; port IN_AIN4
IN_AIN4_N: J8.2 R129.2 ; port IN_AIN4_N
IN_AIN5: J9.1 ; port IN_AIN5
IN_AIN5_N: J9.2 R130.2 ; port IN_AIN5_N
IN_AIN6: J4.1 ; port IN_AIN6
IN_AIN6_N: J4.2 R117.2 ; port IN_AIN6_N
IN_AIN7: J3.1 ; port IN_AIN7
IN_AIN7_N: J3.2 R116.2 ; port IN_AIN7_N

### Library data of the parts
C1 C2 = 202R18W102KV4E: CAP, CERM, 1000pF, 2KV 10% X7R 1206; Manufacturer: Johanson Dielectrics Inc; Polarized: N; CompType: Capacitor; Cap_F: 0.000000001; Tolerance_%: 0
D7 = SMBJ18CA: TVS 18 VOLT 600 WATT BI-DIR SMB; Manufacturer: Littelfuse Inc
J1-J10 J12-J18 = CON-OSTVN02A150: Terminal Block, 4x1, 2.54mm, TH; Manufacturer: On Shore Technology Inc; SymbolCreator: x0120606
R116-R121 R129 R130 R132 R141 R146-R151 = RC0402JR-070RL: RES, 0 ohm,5%, 0.25W, 1206; Manufacturer: Yageo America; CompType: Resistor; Value_Code: 0000; Tolerance_%: 5; Power_W: 0.1; Value2: 0.125W; VDC_V: 50; TempCo: 200 ppm/C; EIA_Code: E24; U/M: EA
TP22 = TP-040_RND: as TP1 on sheet Pg3  ADC1,ADC2

## Sheet Pg5 ADC1 FILTERS.SchDoc
size 431 x 279 mm; Date: Not shown in title block; ApprovedBy: Not shown in title block; CheckedBy: Not shown in title block; Author: Not shown in title block; CompanyName: Not shown in title block; Engineer: Not shown in title block; Organization: Not shown in title block; Address1: Not shown in title block; Address2: Not shown in title block; Address3: Not shown in title block; Address4: Not shown in title block; DocumentNumber: 4; Revision: Use project parameter SCH_Rev; SheetNumber: 5; SheetTotal: 8; PageSetup: Record=PageOptions|CenterHorizontal=True|CenterVertical=True|PrintScale=0.64|XCorrection=1.00|YCorrection=1.00|PrintKind=0|BorderSize=5000000|LeftOffset=0|BottomOffset=0|Orientation=2|PaperLength=1000|PaperWidth=1000|Scale=100|PaperSource=15|PrintQuality=600|MediaType=1|DitherType=10|PaperKind=Letter|PrintScaleMode=1
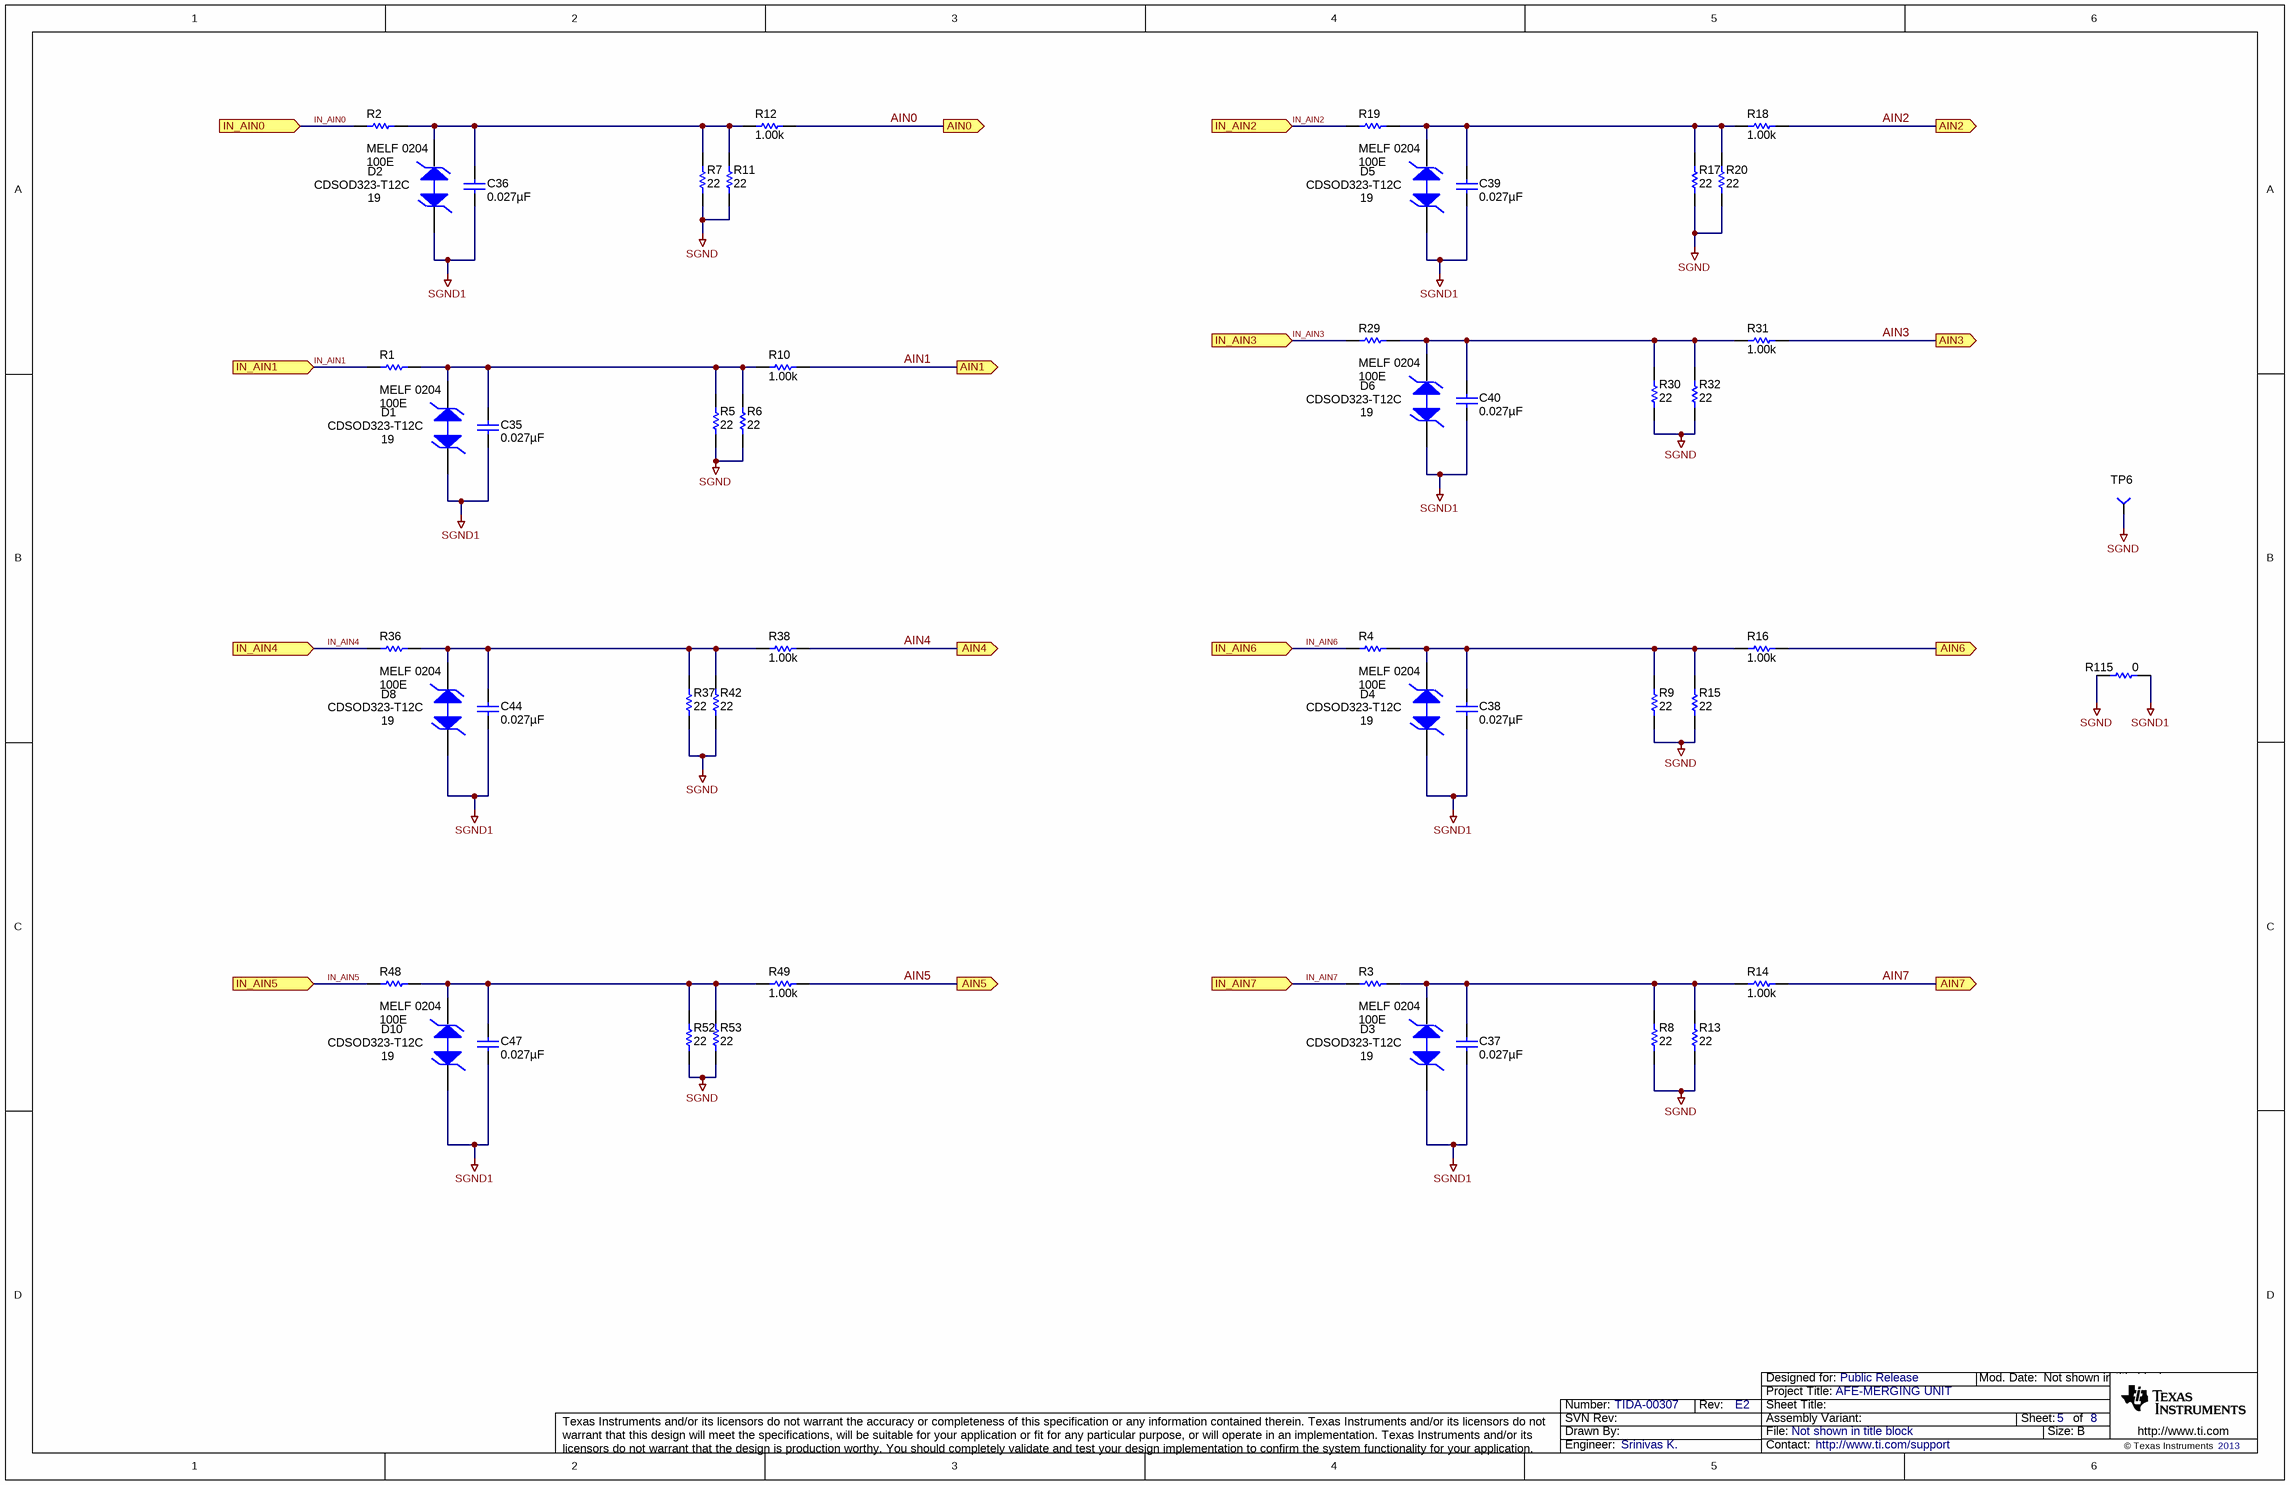
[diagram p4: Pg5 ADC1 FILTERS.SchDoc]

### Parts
C35  ValueDisplayed: 0.027µF  [1206]  (hidden comment: GRM3195C1H273JA01D)
C36  ValueDisplayed: 0.027µF  [1206]  (hidden comment: GRM3195C1H273JA01D)
C37  ValueDisplayed: 0.027µF  [1206]  (hidden comment: GRM3195C1H273JA01D)
C38  ValueDisplayed: 0.027µF  [1206]  (hidden comment: GRM3195C1H273JA01D)
C39  ValueDisplayed: 0.027µF  [1206]  (hidden comment: GRM3195C1H273JA01D)
C40  ValueDisplayed: 0.027µF  [1206]  (hidden comment: GRM3195C1H273JA01D)
C44  ValueDisplayed: 0.027µF  [1206]  (hidden comment: GRM3195C1H273JA01D)
C47  ValueDisplayed: 0.027µF  [1206]  (hidden comment: GRM3195C1H273JA01D)
D1  CDSOD323-T12C  value 19  [sod-323]
D2  CDSOD323-T12C  value 19  [sod-323]
D3  CDSOD323-T12C  value 19  [sod-323]
D4  CDSOD323-T12C  value 19  [sod-323]
D5  CDSOD323-T12C  value 19  [sod-323]
D6  CDSOD323-T12C  value 19  [sod-323]
D8  CDSOD323-T12C  value 19  [sod-323]
D10  CDSOD323-T12C  value 19  [sod-323]
R1  value 100E  PackageReference: MELF 0204  [1206]  (hidden comment: MMA02040C1000FB300)
R2  value 100E  PackageReference: MELF 0204  [1206]  (hidden comment: MMA02040C1000FB300)
R3  value 100E  PackageReference: MELF 0204  [1206]  (hidden comment: MMA02040C1000FB300)
R4  value 100E  PackageReference: MELF 0204  [1206]  (hidden comment: MMA02040C1000FB300)
R5  value 22  [0603]  (hidden comment: CRCW060322R0FKEA)
R6  value 22  [0603]  (hidden comment: CRCW060322R0FKEA)
R7  value 22  [0603]  (hidden comment: CRCW060322R0FKEA)
R8  value 22  [0603]  (hidden comment: CRCW060322R0FKEA)
R9  value 22  [0603]  (hidden comment: CRCW060322R0FKEA)
R10  value 1.00k  [0603]  (hidden comment: CRCW06031K00FKEA)
R11  value 22  [0603]  (hidden comment: CRCW060322R0FKEA)
R12  value 1.00k  [0603]  (hidden comment: CRCW06031K00FKEA)
R13  value 22  [0603]  (hidden comment: CRCW060322R0FKEA)
R14  value 1.00k  [0603]  (hidden comment: CRCW06031K00FKEA)
R15  value 22  [0603]  (hidden comment: CRCW060322R0FKEA)
R16  value 1.00k  [0603]  (hidden comment: CRCW06031K00FKEA)
R17  value 22  [0603]  (hidden comment: CRCW060322R0FKEA)
R18  value 1.00k  [0603]  (hidden comment: CRCW06031K00FKEA)
R19  value 100E  PackageReference: MELF 0204  [1206]  (hidden comment: MMA02040C1000FB300)
R20  value 22  [0603]  (hidden comment: CRCW060322R0FKEA)
R29  value 100E  PackageReference: MELF 0204  [1206]  (hidden comment: MMA02040C1000FB300)
R30  value 22  [0603]  (hidden comment: CRCW060322R0FKEA)
R31  value 1.00k  [0603]  (hidden comment: CRCW06031K00FKEA)
R32  value 22  [0603]  (hidden comment: CRCW060322R0FKEA)
R36  value 100E  PackageReference: MELF 0204  [1206]  (hidden comment: MMA02040C1000FB300)
R37  value 22  [0603]  (hidden comment: CRCW060322R0FKEA)
R38  value 1.00k  [0603]  (hidden comment: CRCW06031K00FKEA)
R42  value 22  [0603]  (hidden comment: CRCW060322R0FKEA)
R48  value 100E  PackageReference: MELF 0204  [1206]  (hidden comment: MMA02040C1000FB300)
R49  value 1.00k  [0603]  (hidden comment: CRCW06031K00FKEA)
R52  value 22  [0603]  (hidden comment: CRCW060322R0FKEA)
R53  value 22  [0603]  (hidden comment: CRCW060322R0FKEA)
R115  value 0  [1206]  (hidden comment: RC1206JR-070RL)
TP6  TP1_PD40_D0.5_S50  [TP1_PD40_D0.5_S50]  (value not drawn)

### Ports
AIN0 (out), AIN1 (out), AIN2 (out), AIN3 (out), AIN4 (out), AIN5 (out), AIN6 (out), AIN7 (out), IN_AIN0 (in), IN_AIN1 (in), IN_AIN2 (in), IN_AIN3 (in), IN_AIN4 (in), IN_AIN5 (in), IN_AIN6 (in), IN_AIN7 (in)

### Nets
SGND: R5.1 R6.1 R7.1 R8.1 R9.1 R11.1 R13.1 R15.1 R17.1 R20.1 R30.1 R32.1 R37.1 R42.1 R52.1 R53.1 R115.1 TP6.1
SGND1: C35.2 C36.2 C37.2 C38.2 C39.2 C40.2 C44.2 C47.2 D1.2 D2.2 D3.2 D4.2 D5.2 D6.2 D8.2 D10.2 R115.2
AIN0: R12.2 ; port AIN0
AIN1: R10.2 ; port AIN1
AIN2: R18.2 ; port AIN2
AIN3: R31.2 ; port AIN3
AIN4: R38.2 ; port AIN4
AIN5: R49.2 ; port AIN5
AIN6: R16.2 ; port AIN6
AIN7: R14.2 ; port AIN7
IN_AIN0: R2.1 ; port IN_AIN0
IN_AIN1: R1.1 ; port IN_AIN1
IN_AIN2: R19.1 ; port IN_AIN2
IN_AIN3: R29.1 ; port IN_AIN3
IN_AIN4: R36.1 ; port IN_AIN4
IN_AIN5: R48.1 ; port IN_AIN5
IN_AIN6: R4.1 ; port IN_AIN6
IN_AIN7: R3.1 ; port IN_AIN7
NetC35_1: C35.1 D1.1 R1.2 R5.2 R6.2 R10.1
NetC36_1: C36.1 D2.1 R2.2 R7.2 R11.2 R12.1
NetC37_1: C37.1 D3.1 R3.2 R8.2 R13.2 R14.1
NetC38_1: C38.1 D4.1 R4.2 R9.2 R15.2 R16.1
NetC39_1: C39.1 D5.1 R17.2 R18.1 R19.2 R20.2
NetC40_1: C40.1 D6.1 R29.2 R30.2 R31.1 R32.2
NetC44_1: C44.1 D8.1 R36.2 R37.2 R38.1 R42.2
NetC47_1: C47.1 D10.1 R48.2 R49.1 R52.2 R53.2

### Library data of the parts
C35-C40 C44 C47 = GRM3195C1H273JA01D: CAP, CERM, 0.027uF, 50V, +/-5%, C0G/NP0, 1206; Manufacturer: MuRata; Polarized: N; CompType: Capacitor; U/M: EA; Cap_F: 0.000000027; Tolerance_%: 5; Value1: Unknown; VDC_V: 50; TaMin_C: -55; TaMax_C: 125
D1-D6 D8 D10 = CDSOD323-T15SC: Diode, TVS, ARRAY, 19V, SOD323; Manufacturer: Bourns Inc.
R1-R4 R19 R29 R36 R48 = MMA02040C1000FB300: RES 100 OHM .4W 1% 0204 MELF; Manufacturer: Vishay Beyschlag; CompType: Resistor; Power_W: 0.5
R5-R9 R11 R13 R15 R17 R20 R30 R32 R37 R42 R52 R53 = CRCW060322R0JNEA: RES, 22 ohm, 1%, 0.1W, 0603; Manufacturer: Vishay-Dale; CompType: Resistor; Value_Code: 22R0; Tolerance_%: 1; Power_W: 0.1; VDC_V: 75; TempCo: 200 ppm/C; EIA_Code: E24; U/M: EA
R10 R12 R14 R16 R18 R31 R38 R49 = CRCW06031K00FKEA: RES, 1.00k ohm, 1%, 0.1W, 0603; Manufacturer: Vishay-Dale; CompType: Resistor; Res_ohm: 1000; Value_Code: 1k00; Tolerance_%: 1; Power_W: 0.1; VDC_V: 75; TempCo: 100 ppm/C; EIA_Code: E96; U/M: EA
R115 = RC0402JR-070RL: as R116 on sheet Pg4 ADC1,ADC2 INPUTS
TP6 = TP-040_RND: as TP1 on sheet Pg3  ADC1,ADC2

## Sheet Pg6 ADC2 FILTERS.SchDoc
size 431 x 279 mm; Date: Not shown in title block; ApprovedBy: Not shown in title block; CheckedBy: Not shown in title block; Author: Not shown in title block; CompanyName: Not shown in title block; Engineer: Not shown in title block; Organization: Not shown in title block; Address1: Not shown in title block; Address2: Not shown in title block; Address3: Not shown in title block; Address4: Not shown in title block; DocumentNumber: 7; Revision: Use project parameter SCH_Rev; SheetNumber: 6; SheetTotal: 8; PageSetup: Record=PageOptions|CenterHorizontal=True|CenterVertical=True|PrintScale=0.64|XCorrection=1.00|YCorrection=1.00|PrintKind=0|BorderSize=5000000|LeftOffset=0|BottomOffset=0|Orientation=2|PaperLength=1000|PaperWidth=1000|Scale=100|PaperSource=15|PrintQuality=600|MediaType=1|DitherType=10|PaperKind=Letter|PrintScaleMode=1
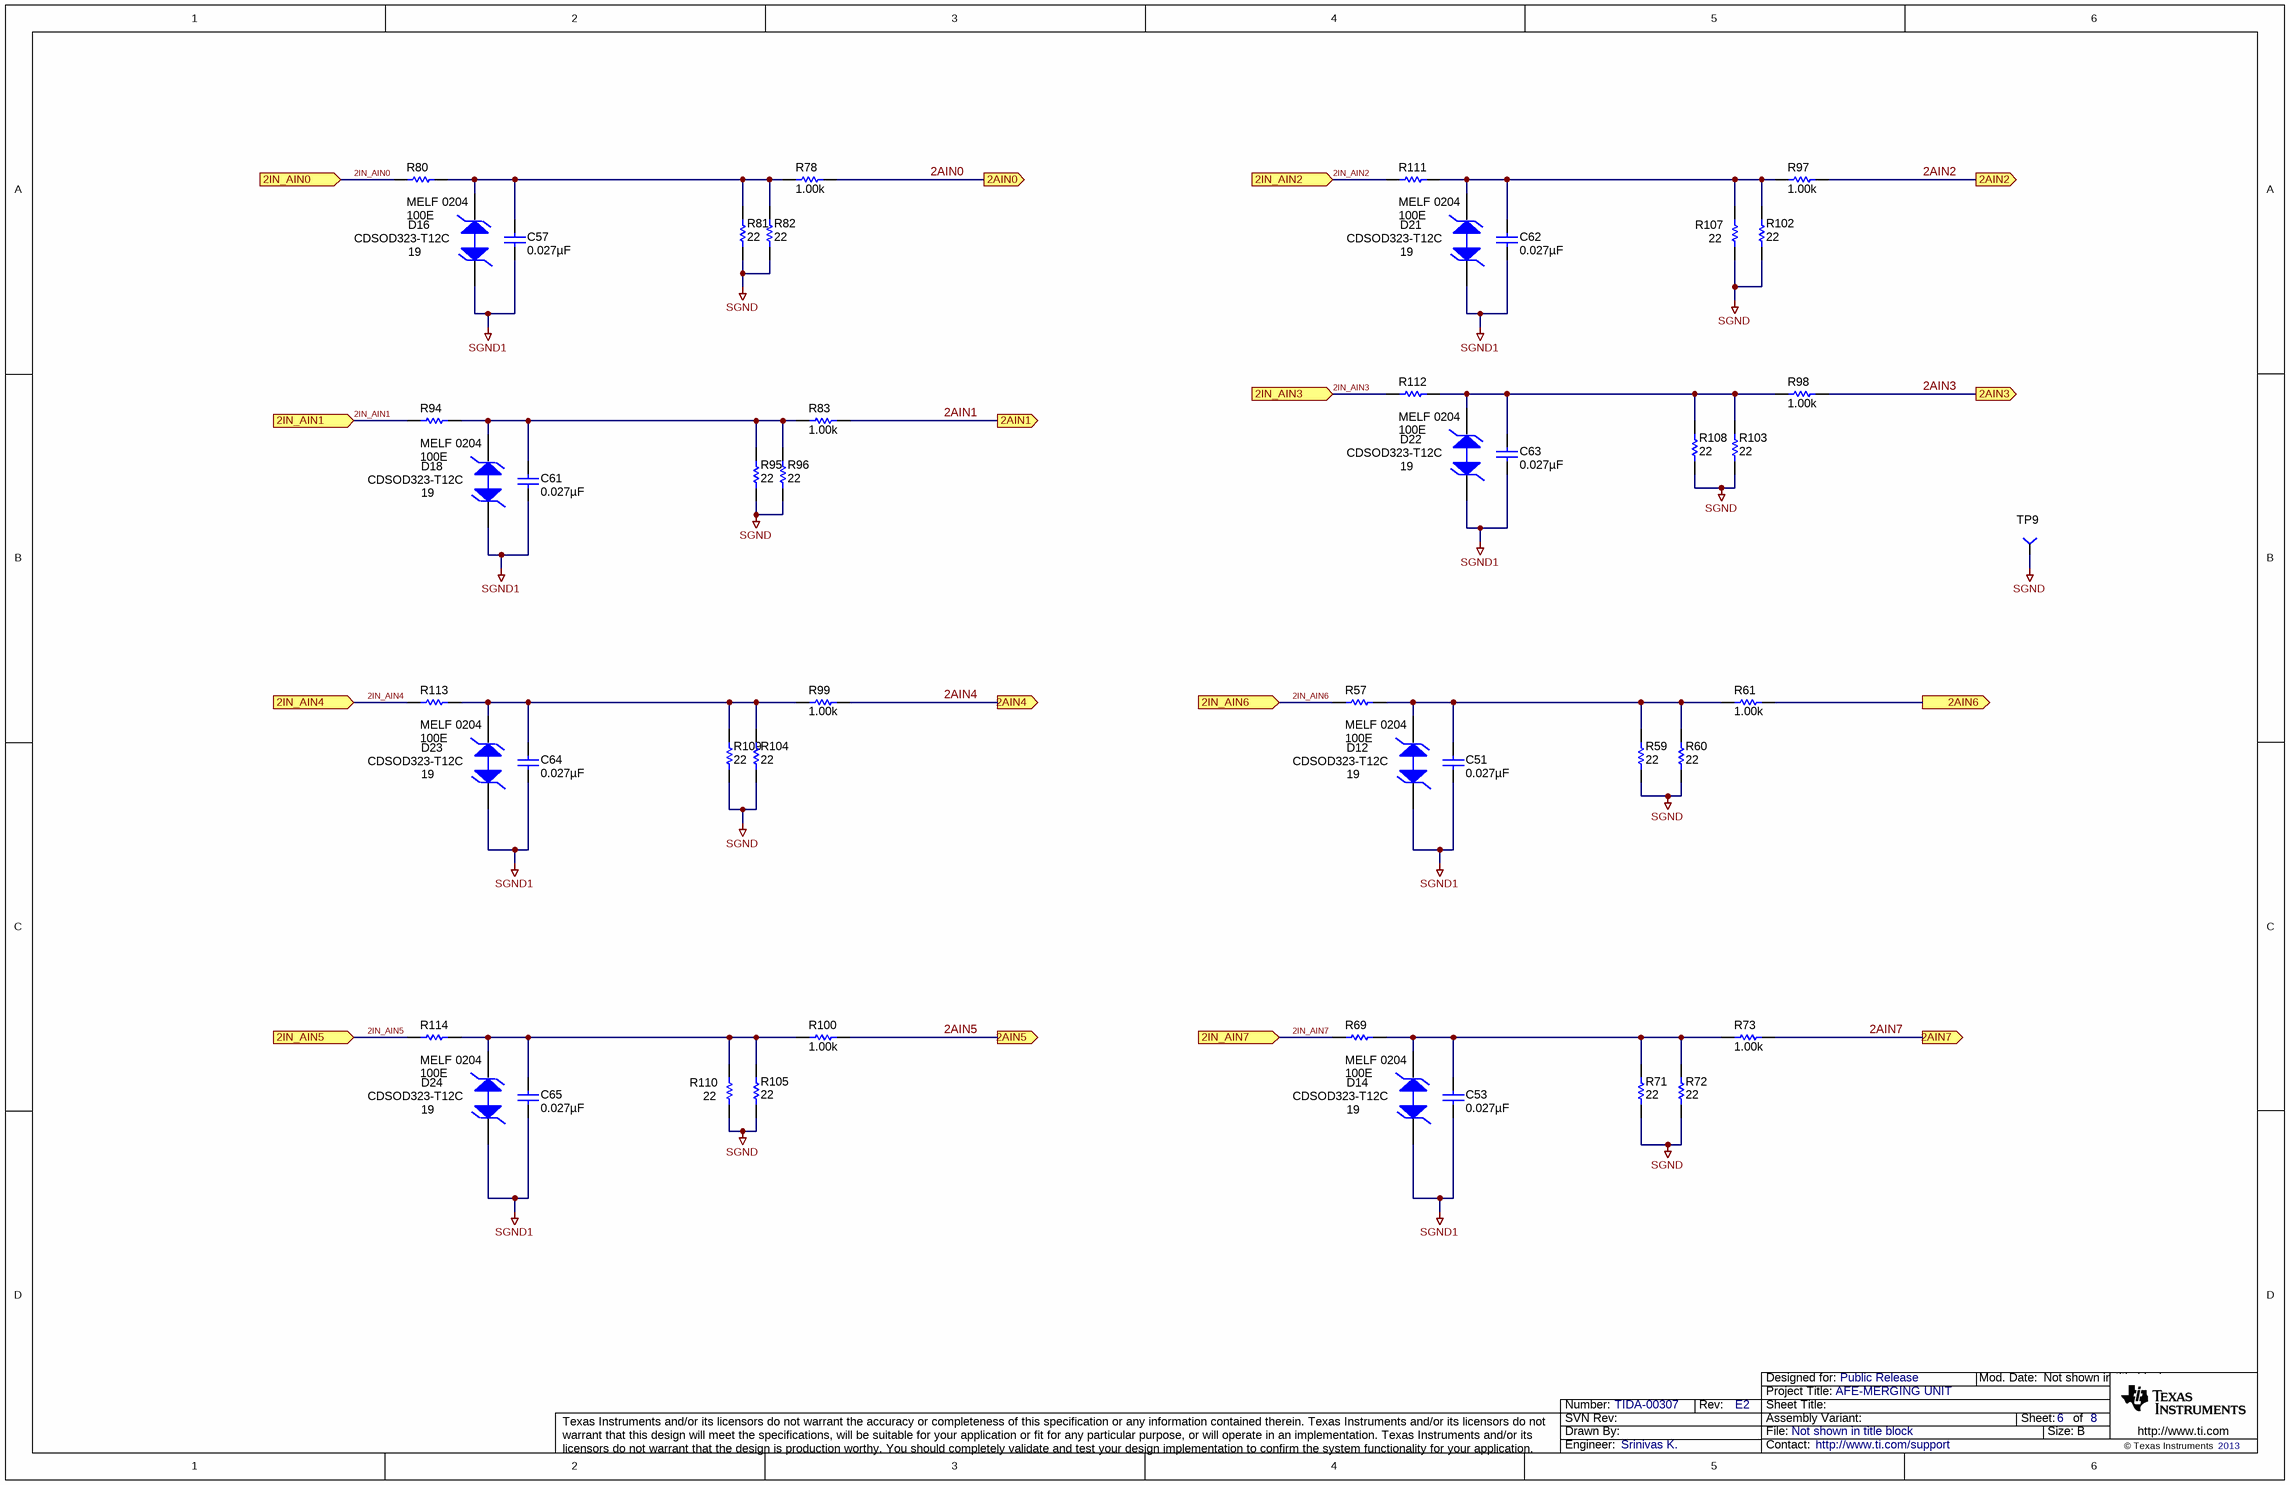
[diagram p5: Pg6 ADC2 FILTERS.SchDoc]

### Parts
C51  ValueDisplayed: 0.027µF  [1206]  (hidden comment: GRM3195C1H273JA01D)
C53  ValueDisplayed: 0.027µF  [1206]  (hidden comment: GRM3195C1H273JA01D)
C57  ValueDisplayed: 0.027µF  [1206]  (hidden comment: GRM3195C1H273JA01D)
C61  ValueDisplayed: 0.027µF  [1206]  (hidden comment: GRM3195C1H273JA01D)
C62  ValueDisplayed: 0.027µF  [1206]  (hidden comment: GRM3195C1H273JA01D)
C63  ValueDisplayed: 0.027µF  [1206]  (hidden comment: GRM3195C1H273JA01D)
C64  ValueDisplayed: 0.027µF  [1206]  (hidden comment: GRM3195C1H273JA01D)
C65  ValueDisplayed: 0.027µF  [1206]  (hidden comment: GRM3195C1H273JA01D)
D12  CDSOD323-T12C  value 19  [sod-323]
D14  CDSOD323-T12C  value 19  [sod-323]
D16  CDSOD323-T12C  value 19  [sod-323]
D18  CDSOD323-T12C  value 19  [sod-323]
D21  CDSOD323-T12C  value 19  [sod-323]
D22  CDSOD323-T12C  value 19  [sod-323]
D23  CDSOD323-T12C  value 19  [sod-323]
D24  CDSOD323-T12C  value 19  [sod-323]
R57  value 100E  PackageReference: MELF 0204  [1206]  (hidden comment: MMA02040C1000FB300)
R59  value 22  [0603]  (hidden comment: CRCW060322R0FKEA)
R60  value 22  [0603]  (hidden comment: CRCW060322R0FKEA)
R61  value 1.00k  [0603]  (hidden comment: CRCW06031K00FKEA)
R69  value 100E  PackageReference: MELF 0204  [1206]  (hidden comment: MMA02040C1000FB300)
R71  value 22  [0603]  (hidden comment: CRCW060322R0FKEA)
R72  value 22  [0603]  (hidden comment: CRCW060322R0FKEA)
R73  value 1.00k  [0603]  (hidden comment: CRCW06031K00FKEA)
R78  value 1.00k  [0603]  (hidden comment: CRCW06031K00FKEA)
R80  value 100E  PackageReference: MELF 0204  [1206]  (hidden comment: MMA02040C1000FB300)
R81  value 22  [0603]  (hidden comment: CRCW060322R0FKEA)
R82  value 22  [0603]  (hidden comment: CRCW060322R0FKEA)
R83  value 1.00k  [0603]  (hidden comment: CRCW06031K00FKEA)
R94  value 100E  PackageReference: MELF 0204  [1206]  (hidden comment: MMA02040C1000FB300)
R95  value 22  [0603]  (hidden comment: CRCW060322R0FKEA)
R96  value 22  [0603]  (hidden comment: CRCW060322R0FKEA)
R97  value 1.00k  [0603]  (hidden comment: CRCW06031K00FKEA)
R98  value 1.00k  [0603]  (hidden comment: CRCW06031K00FKEA)
R99  value 1.00k  [0603]  (hidden comment: CRCW06031K00FKEA)
R100  value 1.00k  [0603]  (hidden comment: CRCW06031K00FKEA)
R102  value 22  [0603]  (hidden comment: CRCW060322R0FKEA)
R103  value 22  [0603]  (hidden comment: CRCW060322R0FKEA)
R104  value 22  [0603]  (hidden comment: CRCW060322R0FKEA)
R105  value 22  [0603]  (hidden comment: CRCW060322R0FKEA)
R107  value 22  [0603]  (hidden comment: CRCW060322R0FKEA)
R108  value 22  [0603]  (hidden comment: CRCW060322R0FKEA)
R109  value 22  [0603]  (hidden comment: CRCW060322R0FKEA)
R110  value 22  [0603]  (hidden comment: CRCW060322R0FKEA)
R111  value 100E  PackageReference: MELF 0204  [1206]  (hidden comment: MMA02040C1000FB300)
R112  value 100E  PackageReference: MELF 0204  [1206]  (hidden comment: MMA02040C1000FB300)
R113  value 100E  PackageReference: MELF 0204  [1206]  (hidden comment: MMA02040C1000FB300)
R114  value 100E  PackageReference: MELF 0204  [1206]  (hidden comment: MMA02040C1000FB300)
TP9  TP1_PD40_D0.5_S50  [TP1_PD40_D0.5_S50]  (value not drawn)

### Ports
2AIN0 (out), 2AIN1 (out), 2AIN2 (out), 2AIN3 (out), 2AIN4 (out), 2AIN5 (out), 2AIN6 (out), 2AIN7 (out), 2IN_AIN0 (in), 2IN_AIN1 (in), 2IN_AIN2 (in), 2IN_AIN3 (in), 2IN_AIN4 (in), 2IN_AIN5 (in), 2IN_AIN6 (in), 2IN_AIN7 (in)

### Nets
SGND: R59.1 R60.1 R71.1 R72.1 R81.1 R82.1 R95.1 R96.1 R102.1 R103.1 R104.1 R105.1 R107.1 R108.1 R109.1 R110.1 TP9.1
SGND1: C51.2 C53.2 C57.2 C61.2 C62.2 C63.2 C64.2 C65.2 D12.2 D14.2 D16.2 D18.2 D21.2 D22.2 D23.2 D24.2
2AIN0: R78.2 ; port 2AIN0
2AIN1: R83.2 ; port 2AIN1
2AIN2: R97.2 ; port 2AIN2
2AIN3: R98.2 ; port 2AIN3
2AIN4: R99.2 ; port 2AIN4
2AIN5: R100.2 ; port 2AIN5
2AIN6: R61.2 ; port 2AIN6
2AIN7: R73.2 ; port 2AIN7
2IN_AIN0: R80.1 ; port 2IN_AIN0
2IN_AIN1: R94.1 ; port 2IN_AIN1
2IN_AIN2: R111.1 ; port 2IN_AIN2
2IN_AIN3: R112.1 ; port 2IN_AIN3
2IN_AIN4: R113.1 ; port 2IN_AIN4
2IN_AIN5: R114.1 ; port 2IN_AIN5
2IN_AIN6: R57.1 ; port 2IN_AIN6
2IN_AIN7: R69.1 ; port 2IN_AIN7
NetC51_1: C51.1 D12.1 R57.2 R59.2 R60.2 R61.1
NetC53_1: C53.1 D14.1 R69.2 R71.2 R72.2 R73.1
NetC57_1: C57.1 D16.1 R78.1 R80.2 R81.2 R82.2
NetC61_1: C61.1 D18.1 R83.1 R94.2 R95.2 R96.2
NetC62_1: C62.1 D21.1 R97.1 R102.2 R107.2 R111.2
NetC63_1: C63.1 D22.1 R98.1 R103.2 R108.2 R112.2
NetC64_1: C64.1 D23.1 R99.1 R104.2 R109.2 R113.2
NetC65_1: C65.1 D24.1 R100.1 R105.2 R110.2 R114.2

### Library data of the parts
C51 C53 C57 C61-C65 = GRM3195C1H273JA01D: as C35 on sheet Pg5 ADC1 FILTERS
D12 D14 D16 D18 D21-D24 = CDSOD323-T15SC: as D1 on sheet Pg5 ADC1 FILTERS
R57 R69 R80 R94 R111-R114 = MMA02040C1000FB300: as R1 on sheet Pg5 ADC1 FILTERS
R59 R60 R71 R72 R81 R82 R95 R96 R102-R105 R107-R110 = CRCW060322R0JNEA: as R5 on sheet Pg5 ADC1 FILTERS
R61 R73 R78 R83 R97-R100 = CRCW06031K00FKEA: as R10 on sheet Pg5 ADC1 FILTERS
TP9 = TP-040_RND: as TP1 on sheet Pg3  ADC1,ADC2

## Sheet Pg7 Power Supply.SchDoc
size 431 x 279 mm; Date: Not shown in title block; ApprovedBy: Not shown in title block; CheckedBy: Not shown in title block; Author: Not shown in title block; CompanyName: Not shown in title block; Engineer: Not shown in title block; Organization: Not shown in title block; Address1: Not shown in title block; Address2: Not shown in title block; Address3: Not shown in title block; Address4: Not shown in title block; DocumentNumber: 6; Revision: Use project parameter SCH_Rev; SheetNumber: 7; SheetTotal: 8; PageSetup: Record=PageOptions|CenterHorizontal=True|CenterVertical=True|PrintScale=1.00|XCorrection=1.00|YCorrection=1.00|PrintKind=0|BorderSize=5000000|LeftOffset=0|BottomOffset=0|Orientation=2|PaperLength=1000|PaperWidth=1000|Scale=100|PaperSource=15|PrintQuality=600|MediaType=1|DitherType=10|PaperKind=Letter|PrintScaleMode=1
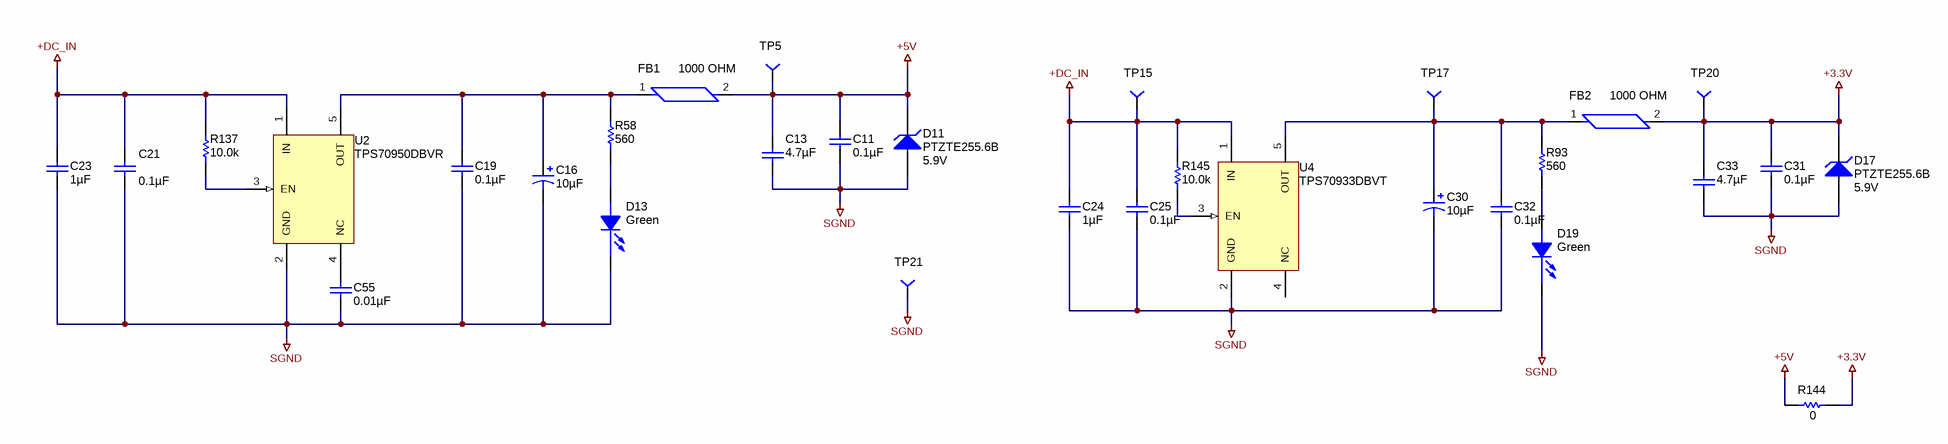
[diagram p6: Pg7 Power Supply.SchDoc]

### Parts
C11  ValueDisplayed: 0.1µF  [0603]  (hidden comment: C0603C104K5RACTU)
C13  ValueDisplayed: 4.7µF  [0805_HV]  (hidden comment: C2012X5R1H475K125AB)
C16  ValueDisplayed: 10µF  [3528-21]  (hidden comment: T491B106K016AT)
C19  ValueDisplayed: 0.1µF  [0603]  (hidden comment: C0603C104K5RACTU)
C21  ValueDisplayed: 0.1µF  [0603]  (hidden comment: C0603C104K5RACTU)
C23  ValueDisplayed: 1µF  [0805]  (hidden comment: 08055C105KAT2A)
C24  ValueDisplayed: 1µF  [0805]  (hidden comment: 08055C105KAT2A)
C25  ValueDisplayed: 0.1µF  [0603]  (hidden comment: C0603C104K5RACTU)
C30  ValueDisplayed: 10µF  [3528-21]  (hidden comment: T491B106K016AT)
C31  ValueDisplayed: 0.1µF  [0603]  (hidden comment: C0603C104K5RACTU)
C32  ValueDisplayed: 0.1µF  [0603]  (hidden comment: C0603C104K5RACTU)
C33  ValueDisplayed: 4.7µF  [0805_HV]  (hidden comment: C2012X5R1H475K125AB)
C55  ValueDisplayed: 0.01µF  [0603]  (hidden comment: C0603C103J5RACTU)
D11  PTZTE255.6B  value 5.9V  [powerDI123]
D13  value Green  [LED0603AA]  (hidden comment: LED_LG L29K-G2J1-24-Z)
D17  PTZTE255.6B  value 5.9V  [powerDI123]
D19  value Green  [LED0603AA]  (hidden comment: LED_LG L29K-G2J1-24-Z)
FB1  1000 OHM  [FB0603]
FB2  1000 OHM  [FB0603]
R58  value 560  [0603]  (hidden comment: CRCW0603560RJNEA)
R93  value 560  [0603]  (hidden comment: CRCW0603560RJNEA)
R137  value 10.0k  [0603]  (hidden comment: CRCW060310K0FKEA)
R144  value 0  [0805]  (hidden comment: RC0805JR-070RL)
R145  value 10.0k  [0603]  (hidden comment: CRCW060310K0FKEA)
TP5  TP1_PD40_D0.5_S50  [TP1_PD40_D0.5_S50]  (value not drawn)
TP15  TP1_PD40_D0.5_S50  [TP1_PD40_D0.5_S50]  (value not drawn)
TP17  TP1_PD40_D0.5_S50  [TP1_PD40_D0.5_S50]  (value not drawn)
TP20  TP1_PD40_D0.5_S50  [TP1_PD40_D0.5_S50]  (value not drawn)
TP21  TP1_PD40_D0.5_S50  [TP1_PD40_D0.5_S50]  (value not drawn)
U2  TPS70950DBVR  [DBV0005A_N]
U4  TPS70933DBVT  [DBV0005A_N]

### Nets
+3.3V: C31.1 C33.1 D17.1(K) FB2.2 R144.2 TP20.1
+5V: C11.1 C13.1 D11.1(K) FB1.2 R144.1 TP5.1
+DC_IN: C21.1 C23.1 C24.1 C25.1 R137.2 R145.2 TP15.1 U2.1(IN) U4.1(IN)
SGND: C11.2 C13.2 C16.2(-) C19.2 C21.2 C23.2 C24.2 C25.2 C30.2(-) C31.2 C32.2 C33.2 C55.2 D11.2(A) D13.1(C) D17.2(A) D19.1(C) TP21.1 U2.2(GND) U4.2(GND)
NetC16_1: C16.1(+) C19.1 FB1.1 R58.2 U2.5(OUT)
NetC30_1: C30.1(+) C32.1 FB2.1 R93.2 TP17.1 U4.5(OUT)
NetC55_1: C55.1 U2.4(NC)
NetD13_2: D13.2(A) R58.1
NetD19_2: D19.2(A) R93.1
NetR137_1: R137.1 U2.3(EN)
NetR145_1: R145.1 U4.3(EN)

Not connected (* = marked no-connect by the designer): U4 4(NC)

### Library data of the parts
C11 C19 C21 C25 C31 C32 = C0603C104K5RACTU: CAP, CERM, 0.1uF, 50V, +/-10%, X7R, 0603; Manufacturer: Kemet; Polarized: N; CompType: Capacitor; U/M: EA; Cap_F: 0.0000001; Tolerance_%: 10; Value1: Unknown; VDC_V: 50; TaMin_C: -55; TaMax_C: 125
C13 C33 = C2012X5R1H475K125AB: CAP, CERM, 4.7uF, 50V, +/-10%, X5R, 0805; Manufacturer: TDK; Polarized: N; CompType: Capacitor; U/M: EA; Cap_F: 0.0000047; Tolerance_%: 10; Value1: Unknown; VDC_V: 50; TaMin_C: -55; TaMax_C: 85; Cap_Case: 0805
C16 C30 = 293D106X9016B2TE3: as C18 on sheet Pg3  ADC1,ADC2
C23 C24 = 08055C105KAT2A: CAP, CERM, 1uF, 50V, +/-10%, X7R, 0805; Manufacturer: AVX; Polarized: N; CompType: Capacitor; U/M: EA; Cap_F: 0.000001; Tolerance_%: 10; Value1: Unknown; VDC_V: 50; TaMin_C: -55; TaMax_C: 125
C55 = C0603C103J5RACTU: CAP, CERM, 0.01uF, 50V, +/-5%, X7R, 0603; Manufacturer: Kemet; Polarized: N; CompType: Capacitor; U/M: EA; Cap_F: 0.00000001; Tolerance_%: 5; Value1: Unknown; VDC_V: 50; TaMin_C: -55; TaMax_C: 125
D11 D17 = PTZTE255.6B: DIODE ZENER 5.9V 1W PMDS; Manufacturer: Rohm Semiconductor; U/M: EA; Vz_V: 5.9
D13 D19 = LED_LG L29K-G2J1-24-Z: as D9 on sheet Pg3  ADC1,ADC2
FB1 FB2 = MMZ1608B102C: as FB3 on sheet Pg3  ADC1,ADC2
R58 R93 = CRCW0603560RJNEA: RES, 560 ohm, 5%, 0.1W, 0603; Manufacturer: Vishay-Dale; CompType: Resistor; Value_Code: 560R; Tolerance_%: 5; Power_W: 0.1; VDC_V: 75; TempCo: 200 ppm/C; EIA_Code: E24; U/M: EA
R137 R145 = CRCW060310K0FKEA: RES, 10.0k ohm, 1%, 0.1W, 0603; Manufacturer: Vishay-Dale; CompType: Resistor; Res_ohm: 10000; Value_Code: 10k0; Tolerance_%: 1; Power_W: 0.1; VDC_V: 75; TempCo: 100 ppm/C; EIA_Code: E96; U/M: EA
R144 = RC0402JR-070RL: RES, 0 ohm,5%, 0.125W, 0805; Manufacturer: Yageo America; CompType: Resistor; Value_Code: 0000; Tolerance_%: 5; Power_W: 0.1; VDC_V: 50; TempCo: 200 ppm/C; EIA_Code: E24; U/M: EA
TP5 TP15 TP17 TP20 TP21 = TP-040_RND: as TP1 on sheet Pg3  ADC1,ADC2
U2 = TPS70950DBVR: IC REG LDO 5V 0.15A SOT23-5; Alternate Manufacturer: None; Manufacturer: Texas Instruments; SymbolCreator: a0411947; U/M: EA
U4 = TPS70933DBVT: IC REG LDO 3.3V 0.15A SOT23-5; Alternate Manufacturer: None; Manufacturer: Texas Instruments; SymbolCreator: a0411947; U/M: EA

## Sheet Pg8 Hardware.SchDoc
size 431 x 279 mm; Date: Not shown in title block; ApprovedBy: Not shown in title block; CheckedBy: Not shown in title block; Author: Not shown in title block; CompanyName: Not shown in title block; Engineer: Not shown in title block; Organization: Not shown in title block; Address1: Not shown in title block; Address2: Not shown in title block; Address3: Not shown in title block; Address4: Not shown in title block; DocumentNumber: 8; Revision: Use project parameter SCH_Rev; SheetNumber: 8; SheetTotal: 8; PageSetup: Record=PageOptions|CenterHorizontal=True|CenterVertical=True|PrintScale=1.00|XCorrection=1.00|YCorrection=1.00|PrintKind=0|BorderSize=5000000|LeftOffset=0|BottomOffset=0|Orientation=2|PaperLength=1000|PaperWidth=1000|Scale=100|PaperSource=15|PrintQuality=600|MediaType=1|DitherType=10|PaperKind=Letter|PrintScaleMode=1
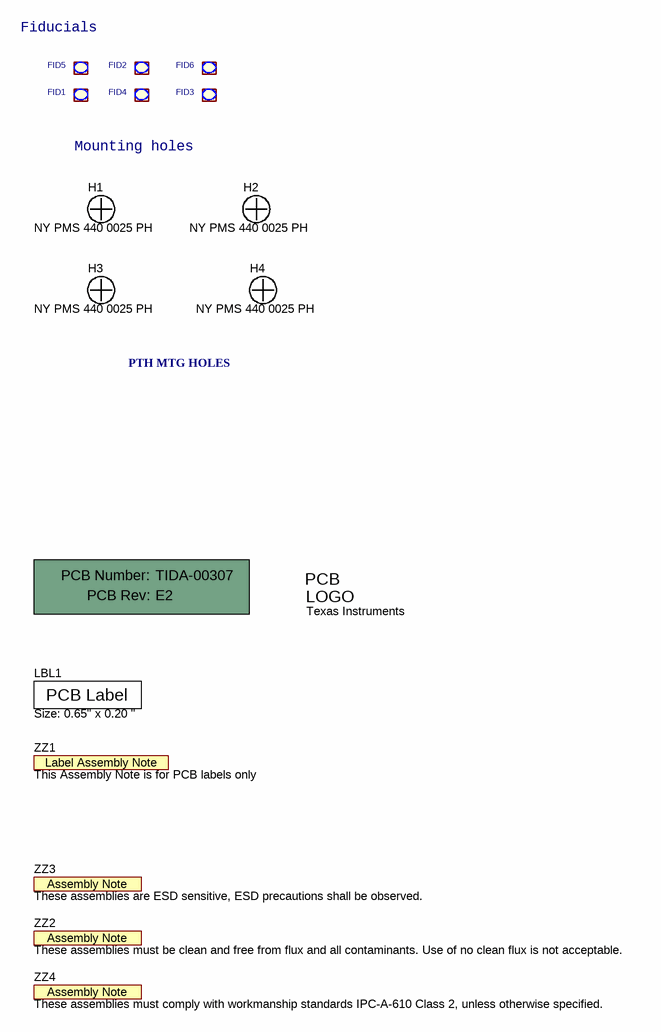
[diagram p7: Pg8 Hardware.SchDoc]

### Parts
!PCB  Printed Circuit Board  (value not drawn)  (mechanical)
FID1  Fiducial40_80  [FID_TOP_40_80BA]  (value not drawn)
FID2  Fiducial40_80  [FID_TOP_40_80BA]  (value not drawn)
FID3  Fiducial40_80  [FID_TOP_40_80BA]  (value not drawn)
FID4  Fiducial40_80  [FID_TOP_40_80BA]  (value not drawn)
FID5  Fiducial40_80  [FID_TOP_40_80BA]  (value not drawn)
FID6  Fiducial40_80  [FID_TOP_40_80BA]  (value not drawn)
H1  NY PMS 440 0025 PH  [NY PMS 440 0025 PH]
H2  NY PMS 440 0025 PH  [NY PMS 440 0025 PH]
H3  NY PMS 440 0025 PH  [NY PMS 440 0025 PH]
H4  NY PMS 440 0025 PH  [NY PMS 440 0025 PH]
LBL1  Size: 0.65" x 0.20 "  [Label_650x200]
Logo1  Texas Instruments  [TI_Stacked_SolderMask_Small]  (no BOM)
ZZ1  This Assembly Note is for PCB labels only  [AssemblyNoteLabel]  (no BOM)
ZZ2  These assemblies must be clean and free from flux and all contaminants. Use of no clean flux is not acceptable.  [AssemblyNote]  (no BOM)
ZZ3  These assemblies are ESD sensitive, ESD precautions shall be observed.  [AssemblyNote]  (no BOM)
ZZ4  These assemblies must comply with workmanship standards IPC-A-610 Class 2, unless otherwise specified.  [AssemblyNote]  (no BOM)

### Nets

Not connected (* = marked no-connect by the designer): FID1 1; FID2 1; FID3 1; FID4 1; FID5 1; FID6 1

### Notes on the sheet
- (near FID5) Fiducials
- Mounting holes
- PTH MTG HOLES

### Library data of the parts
!PCB = PCB: Manufacturer: Any; PartNumber: TIDA-00307; SymbolCreator: a0412235
FID1-FID6 = Fiducial40_0
H1-H4 = NY PMS 440 0025 PH: Machine Screw, Round, #4-40 x 1/4, Nylon, Philips panhead; Manufacturer: B&F Fastener Supply; CompType: Hardware; SymbolCreator: codlsc; U/M: EA
LBL1 = THT-14-423-10: Thermal Transfer Printable Labels, 0.650" W x 0.200" H - 10,000 per roll; Manufacturer: Brady; SymbolCreator: a0412235; CompType: Label
Logo1 = TI_Logo: Texas Instrument Corporate Signature; SymbolCreator: codlsc
ZZ1 = AssemblyNoteLabel: SymbolCreator: a0412235
ZZ2-ZZ4 = AssemblyNote: SymbolCreator: codlsc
